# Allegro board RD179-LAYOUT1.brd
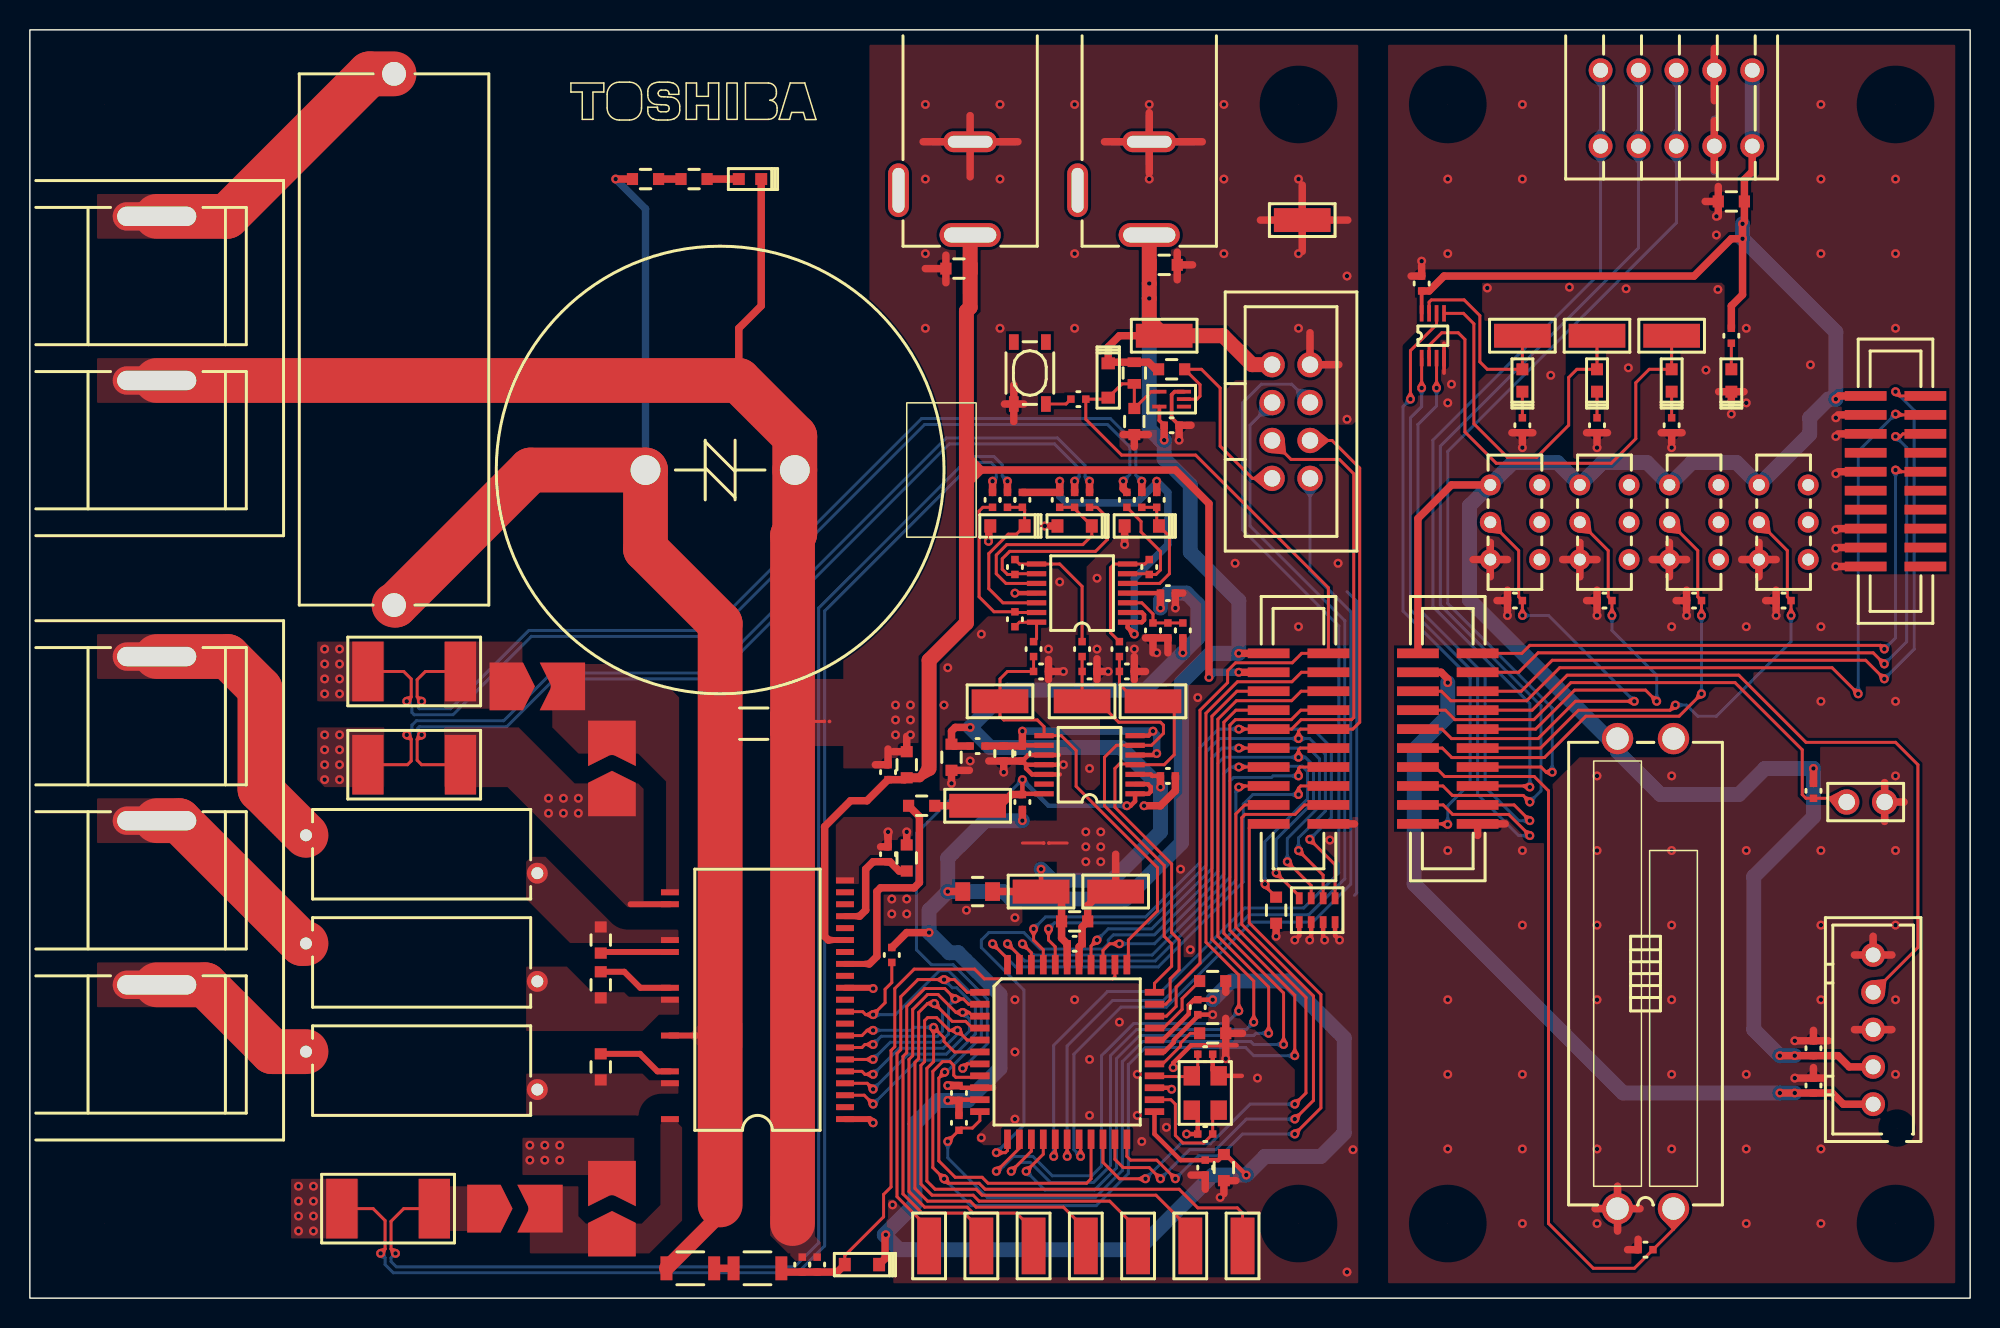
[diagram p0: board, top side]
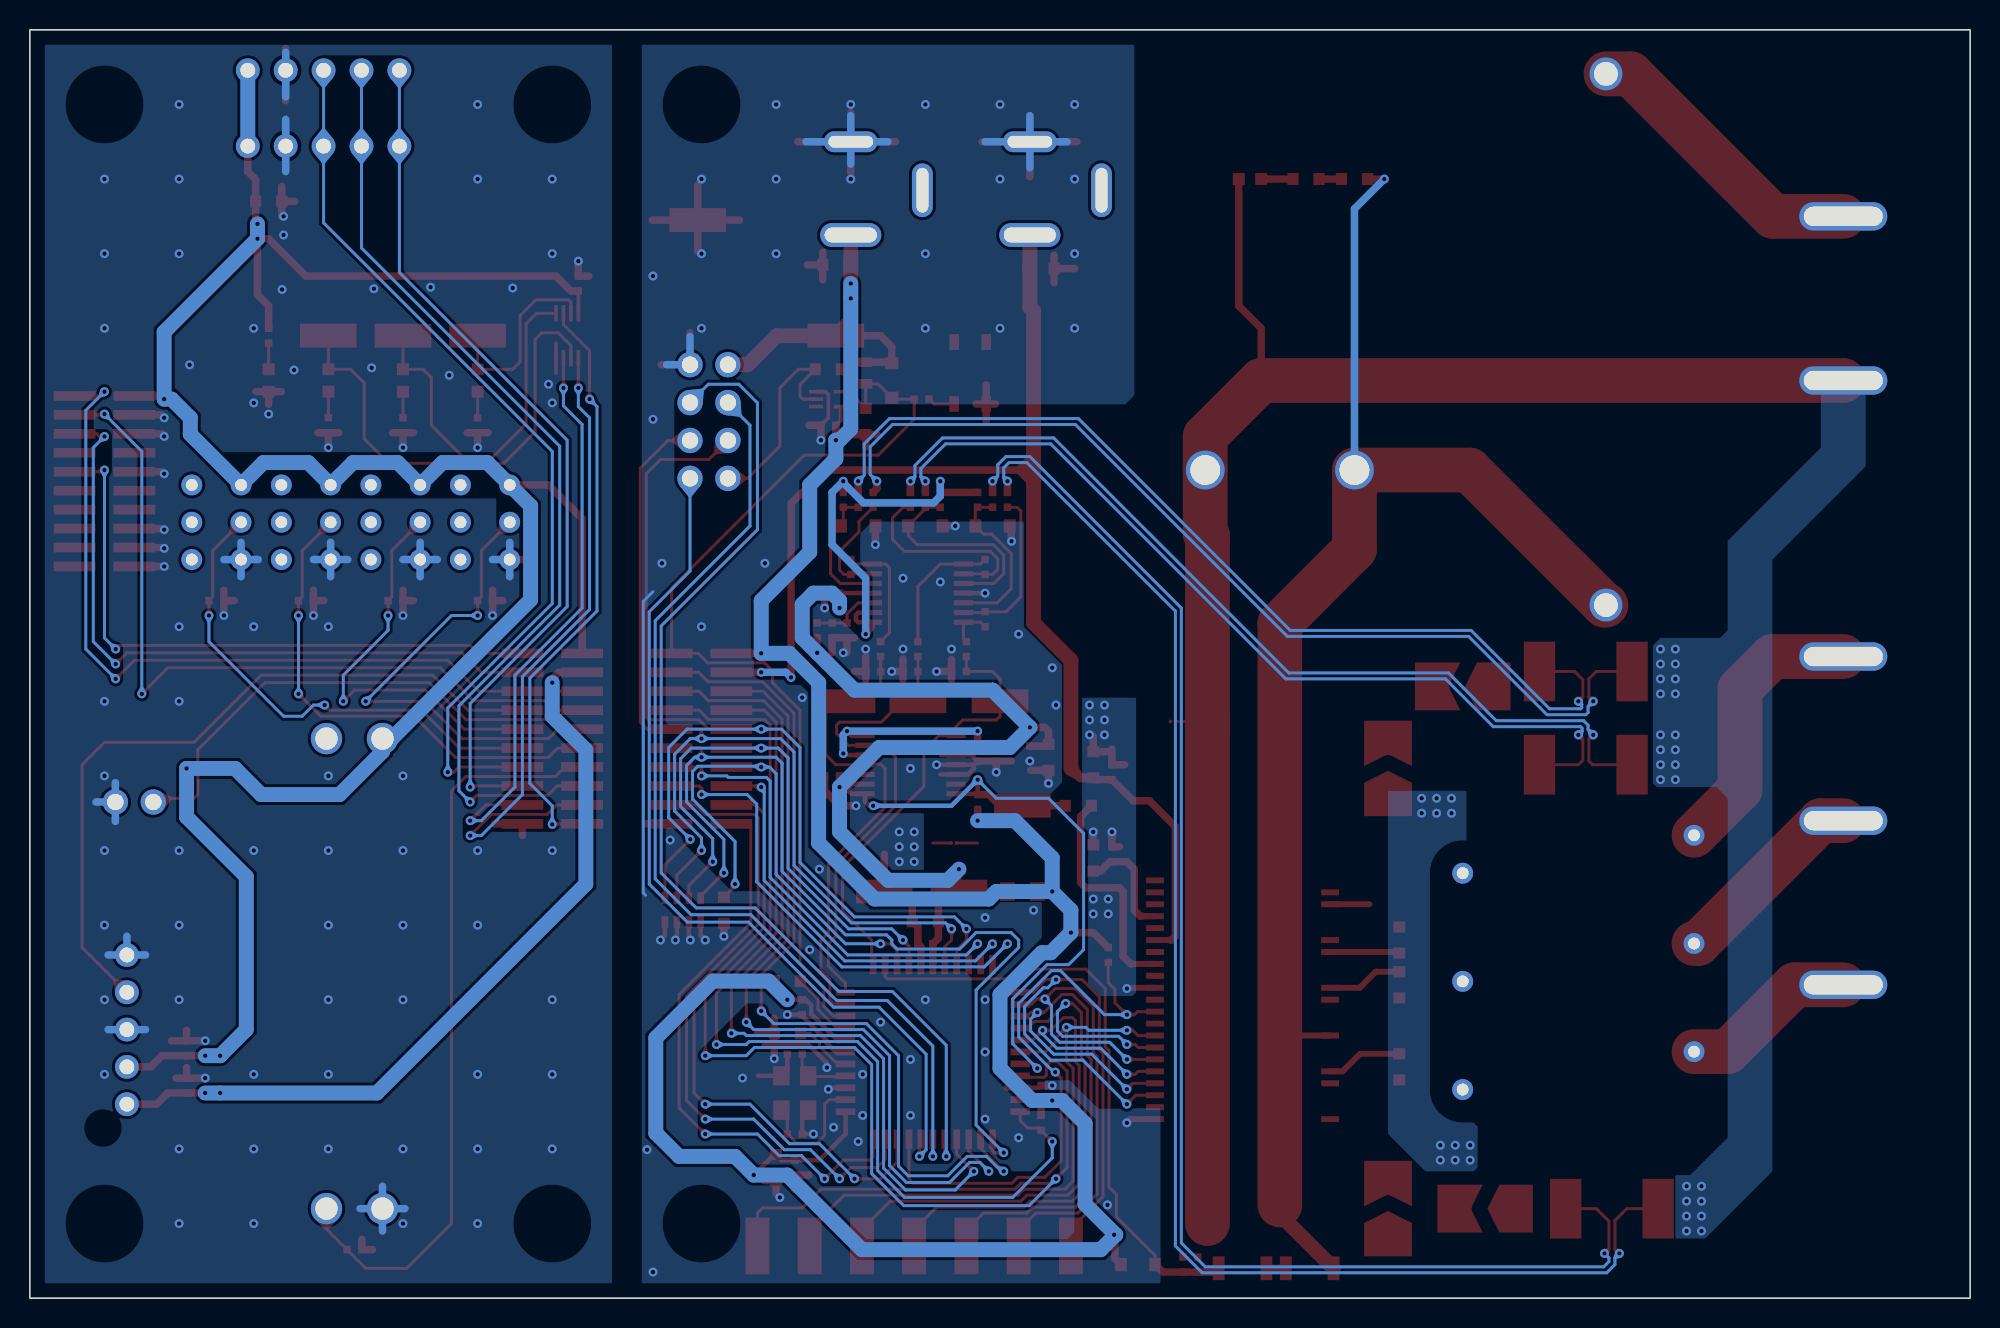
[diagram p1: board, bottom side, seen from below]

Outline 130 x 85 mm; copper layers: TOP, BOTTOM. Coordinates in mm from the lower left corner of the outline.
Outline path: rectangle 0,0 130,85

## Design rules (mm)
constraint set DEFAULT: 

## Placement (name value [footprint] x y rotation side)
C1  -  [CRC1608DEF_R]  58.75 35.75 90 top
C2  -  [CRC1005DEF_R]  57.5 35.25 90 top
C3  -  [CRC1005DEF_R]  62.25 13.75 90 top
C4  -  [CRC1005DEF_R]  78.75 8.75 270 top
C5  -  [CRC1608DEF_R]  80 8.75 270 top
C6  -  [CRC1005DEF_R]  70 23.75 0 top
C7  -  [CRC1608DEF_R]  70 25.25 0 top
C8  -  [CC3216DEF_R]  48.5 38.5 0 top
C9  -  [CRC1608DEF_R]  38.25 15.5 270 top
C10  -  [CRC1608DEF_R]  38.25 21 270 top
C11  -  [CRC1005DEF_R]  76.25 47.25 180 top
C12  -  [CRC1608DEF_R]  38.25 24 90 top
C13  -  [CRC1005DEF_R]  75.25 44.75 90 top
C14  -  [CRC1608DEF_R]  58.75 29.5 90 top
C15  -  [CRC1005DEF_R]  57.5 29.75 90 top
C16  -  [CRC1005DEF_R]  78.75 11 180 top
C18  -  [CRC1608DEF_R]  76 69.25 0 top
C19  -  [CRC1608DEF_R]  62.25 69 180 top
C20  -  [CRC1608DEF_R]  79.25 17.75 0 top
C21  -  [CRC1608DEF_R]  79.25 21.25 0 top
C22  -  [CRC1005DEF_R]  78.25 19.5 270 top
C24  -  [CRC1005DEF_R]  78.75 16.35 0 top
C25  -  [CRC1608DEF_R]  114 73.5 180 top
C26  -  [CRC1005DEF_R]  76.5 58.5 0 top
C27  -  [CRC1608DEF_R]  74 58.75 270 top
C29  -  [CRC1005DEF_R]  93.25 68 90 top
C30  -  [CRC1005DEF_R]  73.5 42 0 top
C31  -  [CRC1005DEF_R]  76.25 35 0 top
C32  -  [CRC1608DEF_R]  61.75 36.25 270 top
C33  -  [CRC1005DEF_R]  71 42 0 top
C34  -  [CRC1005DEF_R]  67.75 42 0 top
C35  -  [CRC1005DEF_R]  66.5 36.5 270 top
C36  -  [DDC300000]  46.25 55.5 0 top
C37  -  [CRC1005DEF_R]  52.75 2.25 90 top
C38  -  [CRC1005DEF_R]  108.25 3.25 180 top
C39  -  [CRC1005DEF_R]  119.5 16.75 90 top
C40  -  [CRC1005DEF_R]  119.5 14.25 90 top
D1  -  [CDUSC05_R]  55.75 2.25 180 top
D2  -  [CDUSC05_R]  72.25 61.5 270 top
D4  -  [CDUSC05_R]  74.5 51.75 180 top
D5  -  [CDUSC05_R]  70 51.75 180 top
D6  -  [CDUSC05_R]  65.5 51.75 180 top
F1  -  [DFU351200]  24.4 64.25 270 top
J1  -  [OTB_650_2P_R00]  8.5 63 270 top
J2  -  [OTB_650_3P_R00]  8.5 28 270 top
J3  -  [2DC_0005D100_R00]  63 71.25 90 top
J4  -  [ML_700_NV_5P_R00]  110 80 180 top
J5  -  [3220_20_0300_00_R00__1]  125 54.75 270 top
J6  -  [3220_20_0300_00_R00__1]  85 37.5 270 top
J7  -  [75869_332LF_R00]  84.5 58.75 270 top
J8  -  [B05B_XASK_1_A_R00]  123.5 18 270 top
J9  -  [3220_20_0300_00_R00__1]  95 37.5 270 top
J10  -  [2DC_0005D100_R00]  75 71.25 90 top
JP1  -  [PH_1X02SG_R00]  123 33.25 0 top
L1  -  [CL2125DEF_R]  63.5 27.25 180 top
L2  -  [DL146001]  26.25 15.25 0 top
L3  -  [DL146001]  26.25 22.5 0 top
L4  -  [DL146001]  26.25 29.75 0 top
LED1  -  [LTST_C190_R00_R]  100 61.5 90 top
LED2  -  [LTST_C190_R00_R]  105 61.5 90 top
LED3  -  [LTST_C190_R00_R]  110 61.5 90 top
LEDP1  -  [LTST_C190_R00_R]  48.25 75 180 top
LEDP2  -  [LTST_C190_R00_R]  114 61.5 90 top
NOREF  -  []  0 0 0 top
NOREF#2  -  []  143 -40 0 top
NOREF#3  -  [unnamed#2]  85 5 0 top
NOREF#4  -  [unnamed#2]  95 80 0 top
NOREF#5  -  [unnamed#2]  125 80 0 top
NOREF#6  -  []  0 -18.5 0 top
NOREF#7  -  [unnamed#2]  85 80 0 top
NOREF#8  -  [unnamed#2]  5 5 0 top
NOREF#9  -  []  36.25 79 0 top
NOREF#10  -  [unnamed#2]  95 5 0 top
NOREF#11  -  [unnamed#2]  5 80 0 top
NOREF#12  -  [unnamed#2]  125 5 0 top
R1  -  [CRC1608DEF_R]  41.25 75 0 top
R2  -  [CR3216DEF_R]  44.25 2 0 top
R3  -  [CRC1608DEF_R]  44.5 75 0 top
R4  -  [CR3216DEF_R]  48.75 2 0 top
R5  -  [CRC1005DEF_R]  51.75 2.25 90 top
R6  -  [CRC1005DEF_R]  77.25 44.75 90 top
R7  -  [CRC1005DEF_R]  76.25 44.75 270 top
R8  -  [CX000275_R]  68.1 30.5 180 top
R9  -  [CX000275_R]  53.4 38.65 180 top
R10  -  [CR643218_R]  24 6 0 top
R11  -  [CR643218_R]  25.75 35.75 0 top
R12  -  [CR643218_R]  25.75 42 0 top
R13  -  [CRC1005DEF_R]  57.75 23 90 top
R14  -  [CRC160858_R]  74 62 90 top
R15  -  [CRC1005DEF_R]  114 64.5 90 top
R16  -  [CRC1005DEF_R]  70.25 60.25 180 top
R17  -  [CRC1005DEF_R]  62.25 11.75 270 top
R18  -  [CRA321633_R]  86.25 26 0 top
R19  -  [CRC1608DEF_R]  83.5 26 270 top
R22  -  [CRC1005DEF_R]  119.5 34 270 top
R25  -  [CRC1005DEF_R]  100 58.5 270 top
R27  -  [CRC1005DEF_R]  75 49 270 top
R28  -  [CRC1005DEF_R]  73.5 53.5 90 top
R29  -  [CRC1005DEF_R]  73 43.5 90 top
R30  -  [CRC1005DEF_R]  105 58.5 270 top
R32  -  [CRC1005DEF_R]  74.5 53.5 90 top
R33  -  [CRC1005DEF_R]  63.5 37 0 top
R34  -  [CRC1005DEF_R]  75.5 53.5 90 top
R35  -  [CRC1005DEF_R]  66.5 33.25 90 top
R36  -  [CRC1005DEF_R]  110 58.5 270 top
R37  -  [CRC1005DEF_R]  66 49 270 top
R38  -  [CRC1005DEF_R]  71 53.5 90 top
R39  -  [CRC1005DEF_R]  70.5 43.5 90 top
R41  -  [CRC1005DEF_R]  70 53.5 90 top
R42  -  [CRC1005DEF_R]  69 53.5 90 top
R43  -  [CRC1608DEF_R]  59.75 33 0 top
R44  -  [CRC1005DEF_R]  66 45.5 90 top
R45  -  [CRC1005DEF_R]  64.5 53.5 90 top
R46  -  [CRC1005DEF_R]  67.25 43.5 90 top
R47  -  [CRC1005DEF_R]  65.5 53.5 90 top
R48  -  [CRC100512_R]  65.25 36.5 270 top
R49  -  [CRC1005DEF_R]  66.5 53.5 90 top
R50  -  [CRC1005DEF_R]  99.5 46.75 180 top
R51  -  [CRC1005DEF_R]  105.5 46.75 180 top
R52  -  [CRC1005DEF_R]  111.5 46.75 180 top
R53  -  [CRC1005DEF_R]  117.5 46.75 180 top
R54  -  [CRC1608DEF_R]  76.5 62.25 0 top
S_SW1  -  [IS_1250_R00]  99.5 52 270 top
S_SW2  -  [IS_1250_R00]  105.5 52 270 top
S_SW3  -  [IS_1250_R00]  111.5 52 270 top
S_SW4  -  [IS_1250_R00]  117.5 52 270 top
SJP1  -  [CJP0002116_R]  39 6 90 top
SJP2  -  [CJP0002116_R]  39 35.5 90 top
SJP3  -  [CJP0002116_R]  32.5 6 0 top
SJP4  -  [CJP0002116_R]  34 41 0 top
SW1  -  [SKRPABE010_R01_R]  67 62 90 top
TP1  -  [CTP321600_R]  81.25 3.5 270 top
TP3  -  [CTP321600_R]  74.25 3.5 270 top
TP4  -  [CTP321600_R]  67.25 3.5 270 top
TP5  -  [CTP321600_R]  60.25 3.5 90 top
TP6  -  [CTP321600_R]  85.25 72.25 180 top
TP7  -  [CTP321600_R]  76 64.5 0 top
TP8  -  [CTP321600_R]  72.75 27.25 180 top
TP9  -  [CTP321600_R]  67.75 27.25 180 top
TP10  -  [CTP321600_R]  75.25 40 180 top
TP11  -  [CTP321600_R]  63.5 33 180 top
TP12  -  [CTP321600_R]  70.5 40 0 top
TP13  -  [CTP321600_R]  65 40 0 top
TP14  -  [CTP321600_R]  63.75 3.5 90 top
TP15  -  [CTP321600_R]  70.75 3.5 90 top
TP16  -  [CTP321600_R]  77.75 3.5 90 top
TST1  -  [CTP321600_R]  100 64.5 0 top
TST2  -  [CTP321600_R]  105 64.5 0 top
TST3  -  [CTP321600_R]  110 64.5 0 top
U1  -  [SP031_0_8_00_R]  48.75 20 90 top
U2  -  [QP044_0_8_02_R]  69.5 16.5 270 top
U5  -  [CIC005_0_5_00_R]  76.5 60.25 90 top
U6  -  [SP014_0_65_06_R]  70.5 47.25 90 top
U7  -  [SP008_0_5_00_R]  94 64.5 0 top
U8  -  [SP014_0_65_06_R]  71 35.75 90 top
VR1  -  [RS15M111J002_R00]  108.25 21.75 90 top
Y1  -  [CXL322568_R]  78.75 13.75 90 top

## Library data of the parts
C1 C5 C7 C9 C10 C12 C14 C18-C21 C25 C27 C32 R1 R3 R19 R43 R54 = CRC-1608-DEF
C2-C4 C6 C11 C13 C15 C16 C22 C24 C26 C29-C31 C33-C35 C37-C40 R5-R7 R13 R15-R17 R22 R25 R27-R30 R32-R39 R41 R42 R44-R47 R49-R53 = CRC-1005-DEF
C8 = CC-3216-DEF
C36 = DDC-3000-00
D1 D2 D4-D6 = CD-USC-05
F1 = DFU-3512-00
J1 = OTB-650-2P_R00
J2 = OTB-650-3P_R00
J3 J10 = 2DC-0005D100_R00
J4 = ML-700-NV-5P_R00
J5 J6 J9 = 3220-20-0300-00_R00
J7 = 75869-332LF_R00
J8 = B05B-XASK-1-A_R00
JP1 = PH-1X02SG_R00
L1 = CL-2125-DEF
L2-L4 = DL-1460-01
LED1-LED3 LEDP1 LEDP2 = LTST-C190_R00
R2 R4 = CR-3216-DEF
R8 R9 = CX-0002-75
R10-R12 = CR-6432-18
R14 = CRC-1608-58
R18 = CRA-3216-33
R48 = CRC-1005-12
S_SW1-S_SW4 = IS-1250_R00
SJP1-SJP4 = CJP-0002-116
SW1 = SKRPABE010_R01
TP1 TP3-TP16 TST1-TST3 = HK-2-G
U1 = TPD4164F
U2 = TMPM374FWUG
U5 = TC7SZ07FE
U6 = AD8648ARUZ: alternate symbols: (U6_SP014_0_65_06_R)
U7 = TC7WH34FK
U8 = TS334IPT
VR1 = RS15M111J002_R00
Y1 = CXL-3225-68

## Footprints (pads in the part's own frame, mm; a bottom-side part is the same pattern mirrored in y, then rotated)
2DC_0005D100_R00
  oval 1.6x4.1 hole 1x3.5: 1(0,0)
  oval 1.4x3.6 hole 0.8x3: 2(6.25,0)
  oval 3.6x1.4 hole 3x0.8: 3(3,4.8)
3220_20_0300_00_R00__1
  rect 0.65x2.8 smd: 1(-5.715,-2) 2(-5.715,2) 3(-4.445,-2) 4(-4.445,2) 5(-3.175,-2) 6(-3.175,2) 7(-1.905,-2) 8(-1.905,2) 9(-0.635,-2) 10(-0.635,2) 11(0.635,-2) 12(0.635,2) 13(1.905,-2) 14(1.905,2) 15(3.175,-2) 16(3.175,2) 17(4.445,-2) 18(4.445,2) 19(5.715,-2) 20(5.715,2)
75869_332LF_R00
  round 1.7 hole 1.1: 1(-3.81,-1.27) 2(-3.81,1.27) 3(-1.27,-1.27) 4(-1.27,1.27) 5(1.27,-1.27) 6(1.27,1.27) 7(3.81,-1.27) 8(3.81,1.27)
B05B_XASK_1_A_R00
  round 0.01 hole 1.2 unplated: (6.6,1.6)
  round 1.6 hole 1: 1(5,0) 2(2.5,0) 3(0,0) 4(-2.5,0) 5(-5,0)
CC3216DEF_R
  rect 1x1.6 smd: 1(-1.6,0) 2(1.6,0)
CDUSC05_R
  rect 0.8x0.9 smd: 1(1.15,0) 3(-1.15,0)
CIC005_0_5_00_R
  rect 0.25x0.95 smd: 1(-0.5,-0.825) 2(0,-0.825) 3(0.5,-0.825) 4(0.5,0.825) 5(-0.5,0.825)
CJP0002116_R
  custom 0.76x0.76 smd: 1(-1.679,0) 2(1.679,0)
CL2125DEF_R
  rect 1x1.25 smd: 1(-1,0) 2(1,0)
CR3216DEF_R
  rect 0.8x1.6 smd: 1(-1.6,0) 2(1.6,0)
CR643218_R
  rect 2.1x4 smd: 1(-3.1,0) 2(3.1,0)
CRA321633_R
  rect 0.45x0.8 smd: 1(-1.2,-0.8) 2(-0.4,-0.8) 3(0.4,-0.8) 4(1.2,-0.8) 5(1.2,0.8) 6(0.4,0.8) 7(-0.4,0.8) 8(-1.2,0.8)
CRC1005DEF_R
  rect 0.5x0.5 smd: 1(-0.5,0) 2(0.5,0)
CRC1608DEF_R
  rect 0.75x0.8 smd: 1(-0.875,0) 2(0.875,0)
CRC100512_R
  rect 0.5x0.6 smd: 1(-0.5,0) 2(0.5,0)
CRC160858_R
  rect 0.65x0.9 smd: 1(-0.725,0) 2(0.725,0)
CTP321600_R
  rect 3.8x1.6 smd: 1(0,0)
CX000275_R
  custom 0.063x0.063 smd: 1(-0.175,0) 2(0.175,0)
CXL322568_R
  rect 1.3x1.1 smd: 1(-1.15,-0.9) 2(1.15,-0.9) 3(1.15,0.9) 4(-1.15,0.9)
DDC300000
  round 2.6 hole 2: 1(-5,0) 2(5,0)
DFU351200
  round 2.2 hole 1.6: 1(-17.8,0) 2(17.8,0)
DL146001
  round 1.4 hole 0.8: 1(-7.75,1.27) 2(7.75,-1.27)
IS_1250_R00
  round 1.4 hole 0.8: 1(-2.5,-1.65) 2(0,-1.65) 3(2.5,-1.65) 4(2.5,1.65) 5(0,1.65) 6(-2.5,1.65)
LTST_C190_R00_R
  rect 0.8x0.8 smd: 1(0.75,0) 2(-0.75,0)
ML_700_NV_5P_R00
  round 1.6 hole 1: 1(-5.4,-2.29) 1-2(-5.4,2.79) 2(-2.86,-2.29) 2-2(-2.86,2.79) 3(-0.32,-2.29) 3-2(-0.32,2.79) 4(2.22,-2.29) 4-2(2.22,2.79) 5(4.76,-2.29) 5-2(4.76,2.79)
OTB_650_2P_R00
  oval 1.9x5.9 hole 1.3x5.3: 1(-9.5,0) 2(1.5,0)
OTB_650_3P_R00
  oval 1.9x5.9 hole 1.3x5.3: 1(-15,0) 2(-4,0) 3(7,0)
PH_1X02SG_R00
  round 1.7 hole 1.1: 1(-1.27,0) 2(1.27,0)
QP044_0_8_02_R
  rect 0.45x1.3 smd: 1(-4,-5.85) 2(-3.2,-5.85) 3(-2.4,-5.85) 4(-1.6,-5.85) 5(-0.8,-5.85) 6(0,-5.85) 7(0.8,-5.85) 8(1.6,-5.85) 9(2.4,-5.85) 10(3.2,-5.85) 11(4,-5.85) 23(4,5.85) 24(3.2,5.85) 25(2.4,5.85) 26(1.6,5.85) 27(0.8,5.85) 28(0,5.85) 29(-0.8,5.85) 30(-1.6,5.85) 31(-2.4,5.85) 32(-3.2,5.85) 33(-4,5.85)
  rect 1.3x0.45 smd: 12(5.85,-4) 13(5.85,-3.2) 14(5.85,-2.4) 15(5.85,-1.6) 16(5.85,-0.8) 17(5.85,0) 18(5.85,0.8) 19(5.85,1.6) 20(5.85,2.4) 21(5.85,3.2) 22(5.85,4) 34(-5.85,4) 35(-5.85,3.2) 36(-5.85,2.4) 37(-5.85,1.6) 38(-5.85,0.8) 39(-5.85,0) 40(-5.85,-0.8) 41(-5.85,-1.6) 42(-5.85,-2.4) 43(-5.85,-3.2) 44(-5.85,-4)
RS15M111J002_R00
  round 2.1 hole 1.5: 1(-15.75,1.875) 2(-15.75,-1.875) 3(15.75,1.875) 4(15.75,-1.875)
SKRPABE010_R01_R
  rect 1.05x0.65 smd: 1(2.075,-1.075) 2(-2.075,-1.075) 3(2.075,1.075) 4(-2.075,1.075)
SP008_0_5_00_R
  rect 0.25x1.1 smd: 1(-0.75,-1.5) 2(-0.25,-1.5) 3(0.25,-1.5) 4(0.75,-1.5) 5(0.75,1.5) 6(0.25,1.5) 7(-0.25,1.5) 8(-0.75,1.5)
SP014_0_65_06_R
  rect 0.35x1.3 smd: 1(-1.95,-3.05) 2(-1.3,-3.05) 3(-0.65,-3.05) 4(0,-3.05) 5(0.65,-3.05) 6(1.3,-3.05) 7(1.95,-3.05) 8(1.95,3.05) 9(1.3,3.05) 10(0.65,3.05) 11(0,3.05) 12(-0.65,3.05) 13(-1.3,3.05) 14(-1.95,3.05)
SP031_0_8_00_R
  rect 0.4x1.2 smd: 1(-8,5.865) 2(-5.6,5.865) 3(-4.8,5.865) 4(-2.4,5.865) 5(0,5.865) 6(0.8,5.865) 7(3.2,5.865) 8(4,5.865) 9(6.4,5.865) 10(7.2,5.865) 11(8,-5.865) 12(7.2,-5.865) 13(6.4,-5.865) 14(5.6,-5.865) 15(4.8,-5.865) 16(4,-5.865) 17(3.2,-5.865) 18(2.4,-5.865) 19(1.6,-5.865) 20(0.8,-5.865) 21(0,-5.865) 22(-0.8,-5.865) 23(-1.6,-5.865) 24(-2.4,-5.865) 25(-3.2,-5.865) 26(-4,-5.865) 27(-4.8,-5.865) 28(-5.6,-5.865) 29(-6.4,-5.865) 30(-7.2,-5.865) 31(-8,-5.865)
unnamed#2
  round 0.01 hole 3.2 unplated: (0,0)

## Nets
AGND: C6.2 C7.2 C11.1 C13.1 C30.2 C31.2 C32.2 C33.2 C34.2 C35.2 D4.1 D5.1 D6.1 R7.2 R8.1 R48.2 TP8.1 U2.38 U6.11 U8.10 U8.11 U8.12
AVDD: C6.1 C7.1 C11.2 C31.1 C32.1 L1.1 R6.1 R33.1 TP9.1 U2.39 U6.4 U8.3
GND: C1.2 C2.2 C3.2 C4.2 C5.2 C14.2 C15.2 C16.2 C18.2 C19.2 C20.2 C21.2 C22.2 C24.2 C26.2 C27.2 J3.2 J6.20 J7.2 J10.2 R8.2 R9.1 R18.1 R18.2 R18.3 R18.4 R19.2 SW1.4 TP6.1 U1.11 U1.20 U1.31 U2.9 U2.25 U2.28 U5.3 Y1.2 Y1.4
GNDX: C25.2 C29.2 C38.2 C39.2 C40.2 J4.2 J4.2-2 J5.3 J5.5 J5.9 J5.15 J5.17 J5.19 J8.3 J8.5 J9.20 JP1.2 LEDP2.2 R25.2 R30.2 R36.2 R50.2 R51.2 R52.2 R53.2 S_SW1.3 S_SW2.3 S_SW3.3 S_SW4.3 U7.4 VR1.1
PGND: C8.2 C36.2 C37.2 J1.2 LEDP1.2 R5.2 R9.2 R10.1 R11.1 R12.1 R28.2 R38.2 R45.2
VDD: C3.1 C4.1 C5.1 C18.1 C22.1 C26.1 D1.3 D2.3 J6.1 J7.1 J10.1 L1.2 R13.2 R14.2 R17.1 R35.1 R54.1 TP7.1 U2.10 U2.23 U2.29 U5.5
VDDX: C25.1 C29.1 C39.1 J4.1 J4.1-2 J5.1 J8.2 J9.1 R15.2 R22.1 S_SW1.1 S_SW2.1 S_SW3.1 S_SW4.1 U7.8 VR1.3
+15: C1.1 C2.1 C19.1 J3.1 J6.3 U1.16
+15X: C40.1 J8.1 J9.3
AD_UP_1: C30.1 R29.1 TP10.1 U2.32 U8.4
AD_VDC_1: C37.1 D1.1 R4.2 R5.1 U2.35
AD_VP_1: C33.1 R39.1 TP12.1 U2.33 U8.6
AD_WP_1: C34.1 R46.1 TP13.1 U2.34 U8.8
COMMD: J6.10 J7.6 R18.6 U2.40
DIAG: R43.1 U1.18
GPIO_MAIN: J7.8 U2.18
KEY_1: J6.9 J7.5 R18.5 U2.41
KEY_3: J6.11 R18.7 U2.37
KEY_4: J6.12 R18.8 U2.12
KEY_A: J6.13 R19.1 U2.36
KEYX_1: J9.9 R50.1 S_SW1.2
KEYX_2: J9.10 R51.1 S_SW2.2
KEYX_3: J9.11 R52.1 S_SW3.2
KEYX_4: J9.12 R53.1 S_SW4.2
KEYX_A: C38.1 J9.13 VR1.2
LED1: J6.17 U2.20
LED1X: J9.17 U7.1
LED2: J6.18 U2.21
LED2X: J9.18 U7.3
LED3: J6.19 U2.22
LED3X: J9.19 U7.6
NBOOT: J6.7 R17.2 U2.11
NBOOTX: J9.7 JP1.1 R22.2
NEMG: R35.2 R43.2 TP11.1 U2.7 U8.1 U8.2 U8.14
NRESET: C27.1 D2.1 J6.2 R14.1 R16.1 U2.31 U5.4
NRESETX: J5.10 J9.2
NRESIN: J7.7 R54.2 U5.2
NSD: R13.1 U1.22 U2.19
NSYNC_SPI: J6.14 U2.42
NSYNC_SPIX: J4.3 J4.3-2 J9.14
RELAY: J6.8 TP1.1 U2.8
RELAYX: J8.4 J9.8
RXD_UA_MCU: J7.3 U2.17
SCLK_SPI: J6.16 U2.44
SCLK_SPIX: J4.5 J4.5-2 J9.16
SDO_SPI: J6.15 U2.43
SDO_SPIX: J4.4 J4.4-2 J9.15
SWCLK: J6.5 U2.14
SWCLKX: J5.4 J9.5
SWDIO: J6.6 U2.15
SWDIOX: J5.2 J9.6
SWV: J6.4 U2.13
SWVX: J5.6 J9.4
TXD_UA_MCU: J7.4 U2.16
UH_1: TP5.1 U1.29 U2.1
UL_1: TP14.1 U1.26 U2.2
VH_1: TP4.1 U1.28 U2.3
VL_1: TP15.1 U1.25 U2.4
VP+: C8.1 C36.1 F1.2 R1.1 R2.1 U1.4
WH_1: TP3.1 U1.27 U2.5
WL_1: TP16.1 U1.24 U2.6
N524300: C24.1 U2.26 Y1.3
N524312: C16.1 U2.24 Y1.1
N530340: C20.1 U2.27
N530678: C21.1 U2.30
N538715: C9.1 U1.3
N538730: C9.2 L2.2 U1.2
N538933: C10.2 L3.2 U1.5
N539007: C10.1 U1.6
N539077: C12.2 L4.2 U1.8
N539151: C12.1 U1.7
N541275: J2.2 L3.1
N541304: J2.3 L2.1
N541340: J2.1 L4.1
N542318: F1.1 J1.1
N545140: SJP2.2 SJP4.2 U1.10
N545527: R11.2 R41.2 SJP1.2 SJP2.1 U1.9
N545615: SJP1.1 SJP3.2 U1.1
N16763341: C14.1 C15.1 U1.14
N16816065: C35.1 R33.2 R48.1 U8.5 U8.7 U8.9
N16817615: D5.3 R41.1 R42.1 U6.10
N16817617: R37.1 R39.2 U6.8
N16817619: R37.2 R38.1 U6.9
N16818945: D4.3 R32.1 R34.1 U6.5
N16818947: R27.1 R29.2 U6.7
N16818953: R27.2 R28.1 U6.6
N16823954: R34.2 R42.2 R49.2 U6.1 U6.2
N16824265: D6.3 R47.1 R49.1 U6.12
N16827190: R12.2 R32.2 SJP4.1
N16827301: R10.2 R47.2 SJP3.1
N16845509: LED1.1 TST1.1 U7.7
N16847149: LED3.1 TST3.1 U7.2
N16847386: LED2.1 TST2.1 U7.5
N16936899: LEDP1.1 R3.2
N16997175: C13.2 R6.2 R7.1 U6.3
N17594442: R44.2 R45.1 U6.13
N17594625: R44.1 R46.2 U6.14
N89949821: R16.2 SW1.2
N168435951: R1.2 R3.1
N168438761: R2.2 R4.1
N168456521: LED1.2 R25.1
N168457540: LED3.2 R36.1
N168470940: LEDP2.1 R15.1
N168482340: LED2.2 R30.1

Pads without a net: J3 3; J5 7 8 11 12 13 14 16 18 20; J10 3; S_SW1 4 5 6; S_SW2 4 5 6; S_SW3 4 5 6; S_SW4 4 5 6; SW1 1 3; U1 12 13 15 17 19 21 23 30; U5 1; U8 13; VR1 4

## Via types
v1: diameter 0.6, hole 0.3, TOP to BOTTOM, 345 vias

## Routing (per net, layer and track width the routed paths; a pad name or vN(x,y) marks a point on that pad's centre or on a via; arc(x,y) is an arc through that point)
AGND: length 43.1
  TOP w0.2: 68.28,30.5 69.5,30.5
  TOP w0.3: 69,35.1 U8.12 67.15,35.1 66.75,35.5 66.75,35.75 ; 66.75,35.75 C35.2 66.9,36.4 U8.10 68.95,36.4 ; 66.75,35.75 U8.11 69,35.75 ; U6.11 v1(66,47.25)
  TOP w0.5: U2.38 70.3,23.55 C6.2 70.5,24.88 C7.2 70.88,26.3 71.83,27.25 TP8.1 72.75,29.75 ; C33.2 v1(72.25,42) ; C33.2 71.5,42.85 ; C33.2 71.5,41.45 ; C13.1 R7.2 76.25,43.25 ; C13.1 75.25,43.25 ; C13.1 74.75,44.25 ; C34.2 v1(69.25,42) ; C34.2 68.25,42.8 ; C34.2 68.25,41.45 ; v1(74.65,33) 75.75,33 76.75,34 C31.2 ; C30.2 74,41.45 ; C30.2 74.75,42 ; C30.2 74,43 ; C35.2 R48.2 ; R48.2 v1(65.25,35.25) ; R48.2 64.25,36 ; D4.1 v1(73.35,50.5) ; D5.1 v1(68,51.75) ; 77.25,47.25 C11.1 v1(76.75,46.25) ; v1(64.22,50.73) 64.25,50.7 64.25,51.65 D6.1 ; v1(61.75,34.5) C32.2 62.95,35.38
  vias: v1(61.25,39.75) v1(61.5,42.25) v1(63,36) v1(63.75,44.5) v1(68.25,43.5) v1(69,48) v1(69.25,35.75) v1(70.75,31.25) v1(70.75,30.25) v1(70.75,29.25) v1(71,35.5) v1(71.5,48.25) v1(71.5,43.5) v1(71.75,31.25) v1(71.75,30.25) v1(71.75,29.25) v1(74,43.5) v1(75.5,43.25)
AVDD: length 71.9
  TOP w0.3: U6.4 C11.2 ; TP9.1 v1(67.75,28.75) ; U8.3 75.1,35.1 75.2,35 C31.1
  TOP w0.5: U2.39 C6.1 69.12,24.12 C7.1 69.12,27.11 68.98,27.25 TP9.1 L1.1 ; R33.1 61.88,37 C32.1 61.75,38 62,38.25 v1(63,38.25) ; C11.2 v1(75.75,46.25) ; C31.1 v1(75.75,34.25) ; R6.1 v1(77.25,43.25)
  BOTTOM w1: v1(75.75,46.25) 75.75,46.75 76.25,47.25 77.5,47.25 78.25,46.5 78.25,44.25 v1(77.25,43.25) 74.75,40.75 65.5,40.75 v1(63,38.25) 64.35,36.9 73.1,36.9 v1(75.75,34.25) 75.75,31.25 72.5,28 68.5,28 v1(67.75,28.75)
GND: length 142.2
  TOP w0.2: R8.2 66.5,30.5
  TOP w0.25: C26.2 76.5,59 76.5,60.55 76.7,60.75 U5.3
  TOP w0.3: v1(77.5,11) C16.2 78.25,12.2 Y1.4 ; v1(85.75,24) 85.85,24.1 R18.2 ; C3.2 62.4,14.1 63.15,14.1 ; R18.3 86.65,24.1 v1(86.75,24) ; C24.2 79.25,15.3 Y1.2 81.2,14.9 ; U2.28 76,16.5 76.65,17.15 76.65,17.3 78.25,18.9 C22.2 v1(79.25,19) ; U2.25 76.4,14.1 v1(76.5,14) ; R18.1 85.05,24.3 v1(84.75,24) ; R18.4 87.45,24.3 v1(87.75,24) ; v1(76.6,15.45) 76.6,15.75 77.8,16.95 80.85,16.95
  TOP w0.4: 64.55,14.1 U2.9 63.15,14.1 ; U1.20 56.45,20.8 v1(56.5,20.75) ; U1.31 56.25,12 v1(56.5,11.75)
  TOP w0.5: 85.77,64.7 J7.2 87.7,62.56 ; C18.2 76.88,68.25 ; C18.2 77.9,69.25 ; C18.2 76.88,70.1 ; v1(77,57.5) C26.2 77.8,58.5 ; v1(57.5,31.25) C15.2 57,30.25 ; 78.75,7.3 C4.2 77.8,8.25 ; SW1.4 65.92,61.2 ; SW1.4 65.92,58.75 ; SW1.4 65.3,59.92 ; SW1.4 66.6,59.92 ; C19.2 60,69 ; C19.2 61.38,68.05 ; C19.2 61.38,69.9 ; R19.2 v1(83.5,24.25) ; J3.2 63,79.25 ; J3.2 63,75.15 ; J3.2 66.2,77.5 ; J3.2 59.85,77.5 ; TP6.1 88.3,72.25 ; TP6.1 85.25,70.15 ; TP6.1 82.45,72.25 ; TP6.1 85.25,74.6 ; v1(61.5,14.25) C3.2 ; J10.2 78.55,77.5 ; J10.2 75,79.45 ; J10.2 72,77.5 ; J10.2 75,75.4 ; 57.5,36.8 C2.2 56.65,35.75 ; 58.75,37.65 C1.2 57.85,36.62 ; C27.2 73.25,57.88 ; C27.2 74.95,57.88 ; C27.2 74,57.05 ; C21.2 80.12,20.5 ; 81.25,17.75 C20.2 ; C20.2 v1(80.12,16.05) ; C20.2 80.12,18.75 ; J6.20 88.75,31.79 ; 80,7 C5.2 80.8,7.88 ; v1(58.75,31.25) C14.2
  BOTTOM w0.2: 88.25,47.35 88.9,46.7 88.9,27.15 88.75,27
  BOTTOM w0.5: J10.2 78,77.5 ; J10.2 72.5,77.5 ; J10.2 75,76 ; J10.2 75,79.25 ; J3.2 60.5,77.5 ; J3.2 63,79.25 ; J3.2 63,75.75 ; J3.2 66,77.5 ; 85.77,64.45 J7.2 87.35,62.56
  vias: v1(57.75,26.75) v1(57.75,25.75) v1(57.8,6.25) v1(58,39.75) v1(58,38.75) v1(58,37.75) v1(58.75,26.75) v1(58.75,25.75) v1(59,39.75) v1(59,38.75) v1(59,37.75) v1(60,80) v1(60,75) v1(60,70) v1(60,65) v1(62.75,26) v1(63.75,10.75) v1(65,80) v1(65,75) v1(65,65) v1(66,25.5) v1(66,20) v1(66,16.5) v1(66,12) v1(70,80) v1(70,70) v1(70,65) v1(70,20) v1(71,16) v1(71,12.25) v1(73,18.5) v1(74.2,15) v1(74.2,12.25) v1(74.5,10.5) v1(75,80) v1(75,75) v1(76.15,11.45) v1(77.1,28.75) v1(77.75,23.35) v1(78.25,40.25) v1(79.75,6.75) v1(80,80) v1(80,75) v1(80,70) v1(80.75,49.25) v1(82.25,14.75) v1(85,75) v1(85,70) v1(85,65) v1(85,45) v1(87.1,30.7) v1(87.65,49.25) v1(88.25,68.5) v1(88.25,58.9) v1(88.25,1.75) v1(88.65,9.95)
GNDX: length 125.5
  TOP w0.25: 94.75,62 U7.4 94.75,64
  TOP w0.5: C25.2 113.12,72.5 ; C25.2 112.25,73.5 ; C25.2 113.12,74.5 ; R30.2 105,57.3 ; R30.2 105.7,58 ; R30.2 104.3,58 ; JP1.2 125.57,33.25 ; JP1.2 124.27,34.55 ; JP1.2 124.27,31.95 ; 107.75,3.95 C38.2 107.05,3.25 ; S_SW2.3 103.85,48.35 ; S_SW2.3 105,49.5 ; S_SW2.3 103.85,50.65 ; S_SW2.3 102.7,49.5 ; VR1.1 107.88,6 ; VR1.1 104.88,6 ; VR1.1 106.38,4.5 ; VR1.1 106.38,7.5 ; S_SW1.3 99,49.5 ; S_SW1.3 97.85,48.35 ; S_SW1.3 97.85,50.65 ; S_SW1.3 96.7,49.5 ; S_SW4.3 117,49.5 ; S_SW4.3 115.85,48.35 ; S_SW4.3 114.7,49.5 ; S_SW4.3 115.85,50.65 ; LEDP2.2 114,59.9 ; LEDP2.2 113.15,60.75 ; LEDP2.2 114.85,60.75 ; J5.17 121.15,50.3 ; S_SW3.3 109.85,48.35 ; S_SW3.3 111,49.5 ; S_SW3.3 108.7,49.5 ; S_SW3.3 109.85,50.65 ; R51.2 105,46.05 ; R51.2 104.3,46.75 ; R51.2 105,47.45 ; R50.2 98.3,46.75 ; R50.2 99,46.05 ; R50.2 99,47.45 ; J5.15 121.15,51.58 ; C39.2 119.5,17.95 ; C39.2 120.5,17.25 ; C39.2 v1(118.25,17.25) ; J5.19 121.15,49.03 ; 112.86,83.75 J4.2 112.86,80.25 ; R52.2 111,47.45 ; R52.2 110.3,46.75 ; R52.2 111,46.05 ; 112.86,75.6 J4.2-2 112.86,78.9 ; R53.2 117,46.05 ; R53.2 116.3,46.75 ; R53.2 117,47.45 ; R36.2 109.3,58 ; R36.2 110.7,58 ; R36.2 110,57.3 ; 93.25,69.2 C29.2 92.55,68.5 ; J5.9 121.15,55.38 ; 97,31.01 J9.20 98.85,31.79 ; J8.5 124.75,23 ; J8.5 123.5,24.25 ; J8.5 122.25,23 ; 122.25,18 J8.3 124.75,18 ; R25.2 100.7,58 ; R25.2 99.3,58 ; R25.2 100,57.3 ; J5.3 121.15,59.2 ; C40.2 119.5,15.45 ; C40.2 v1(118.25,14.75) ; C40.2 120.2,14.75 ; J5.5 121.15,57.92
  BOTTOM w0.5: J8.5 124.75,23 ; J8.5 122.25,23 ; J8.5 123.5,24.25 ; 124.75,18 J8.3 122.25,18 ; S_SW2.3 102.7,49.5 ; S_SW2.3 105,49.5 ; S_SW2.3 103.85,50.65 ; S_SW2.3 103.85,48.35 ; 112.86,83.5 J4.2 112.86,80.5 ; S_SW3.3 111,49.5 ; S_SW3.3 108.7,49.5 ; S_SW3.3 109.85,50.65 ; S_SW3.3 109.85,48.35 ; VR1.1 106.38,4.5 ; VR1.1 107.88,6 ; VR1.1 104.88,6 ; VR1.1 106.38,7.5 ; S_SW4.3 114.7,49.5 ; S_SW4.3 115.85,50.65 ; S_SW4.3 115.85,48.35 ; S_SW4.3 117,49.5 ; 112.86,79 J4.2-2 112.86,75.5 ; JP1.2 125.57,33.25 ; JP1.2 124.27,34.55 ; JP1.2 124.27,31.95 ; S_SW1.3 97.85,48.35 ; S_SW1.3 99,49.5 ; S_SW1.3 97.85,50.65
  vias: v1(93.25,69.5) v1(95,75) v1(95,70) v1(95,60) v1(95,30) v1(95,20) v1(95,15) v1(95,10) v1(95.25,61.25) v1(97.65,67.7) v1(99,45.75) v1(100,80) v1(100,75) v1(100,57) v1(100,30) v1(100,25) v1(100,15) v1(100,10) v1(100,5) v1(101.9,61.85) v1(103.15,67.75) v1(105,57) v1(105,45.75) v1(105,35) v1(105,30) v1(105,25) v1(105,20) v1(105,10) v1(105,5) v1(106.95,67.65) v1(107.1,62.35) v1(110,57) v1(110,45) v1(110,35) v1(110,30) v1(110,25) v1(110,20) v1(110,15) v1(110,10) v1(111,45.75) v1(112.3,62.2) v1(113,72.5) v1(113,71.25) v1(113.1,67.6) v1(114,59.25) v1(115,65) v1(115,60) v1(115,45) v1(115,30) v1(115,15) v1(115,10) v1(115,5) v1(117,45.75) v1(119.3,62.55) v1(120,80) v1(120,75) v1(120,70) v1(120,45) v1(120,40) v1(120,30) v1(120,25) v1(120,20) v1(120,10) v1(120,5) v1(121,59) v1(121,57.75) v1(121,55.25) v1(121,51.5) v1(121,50.25) v1(121,49.03) v1(125,75) v1(125,70) v1(125,65) v1(125,40) v1(125,35) v1(125,30) v1(125,25) v1(125,20) v1(125,15)
PGND: length 338.6
  TOP w0.2: R11.1 25.3,35.75 25.55,36 25.55,37.45 v1(25.25,37.75) ; R12.1 25.05,42 25.55,41.5 25.55,40.3 v1(25.25,40) ; C8.2 50.25,38.65 R9.2 ; v1(23.5,3) 23.8,3.3 23.8,5.2 23,6 R10.1
  TOP w0.5: R28.2 73.25,54.25 v1(73.25,54.75) ; v1(71,54.75) R38.2 ; 47.5,61.5 47.5,65 49,66.5 LEDP1.2 ; v1(64.5,54.75) R45.2
  TOP w3: J1.2 47.5,61.5 51.25,57.75 C36.2 51.25,51.25 51.1,51.1 51.1,5
  BOTTOM w0.2: v1(25.25,40) 25.6,39.65 25.6,39.25 25.75,39.1 28.35,39.1 33.6,44.35 45.75,44.35 59.95,58.55 72.2,58.55 73.7,57.05 73.7,55.2 v1(73.25,54.75) ; v1(25.25,37.75) 25.6,38.1 25.6,38.4 25.9,38.7 31.75,38.7 34.95,41.9 45.65,41.9 61.4,57.65 68.85,57.65 70.7,55.8 70.7,55.05 v1(71,54.75) ; v1(23.5,3) 23.8,2.7 23.8,2.25 24.35,1.7 51.45,1.7 53.25,3.5 53.25,46.05 63.2,56 64.4,56 64.75,55.65 64.75,55 v1(64.5,54.75)
  vias: v1(18,7.5) v1(18,6.5) v1(18,5.5) v1(18,4.5) v1(19,7.5) v1(19,6.5) v1(19,5.5) v1(19,4.5) v1(19.75,43.5) v1(19.75,42.5) v1(19.75,41.5) v1(19.75,40.5) v1(19.75,37.75) v1(19.75,36.75) v1(19.75,35.75) v1(19.75,34.75) v1(20.75,43.5) v1(20.75,42.5) v1(20.75,41.5) v1(20.75,40.5) v1(20.75,37.75) v1(20.75,36.75) v1(20.75,35.75) v1(20.75,34.75)
VDD: length 203.5
  TOP w0.25: U5.5 75.67,58.83 C26.1
  TOP w0.3: U2.10 62.3,13.3 C3.1 ; v1(81.5,8.25) 80.12,9.62 C5.1 79.62,9.25 C4.1 77.1,9.25 75.35,11 U2.23 ; U2.29 75.9,17.3 77.65,19.05 77.65,19.65 78,20 C22.1 v1(79.25,20)
  TOP w0.5: R13.2 58.75,24.5 v1(60.25,24.5) ; R35.1 v1(66.5,32) ; D1.3 57.3,2.65 57.3,4.25 v1(57.35,4.25) ; L1.2 v1(61.5,27.25) ; J6.1 v1(81,43.22) ; v1(61.5,13.25) C3.1 R17.1 ; R54.1 75.42,62.25 74.95,62.73 R14.2 72.33,62.73 D2.3 72.25,63.75 73,64.5 TP7.1 ; C26.1 v1(76,57.5)
  TOP w1: J10.1 v1(75,68) v1(75,67) 75,65.5 TP7.1 79.95,64.5 81.89,62.56 J7.1
  BOTTOM w1: v1(75,68) v1(75,67) 75,58.25 75.75,57.5 v1(76,57.5) 76,56.25 77.75,54.5 77.75,50 81,46.75 v1(81,43.22) 79.11,43.22 77.15,41.25 77.15,30.5 73.4,26.75 65.75,26.75 65.25,27.25 v1(61.5,27.25) ; 57.25,4.25 58.25,3.25 74.25,3.25 79.25,8.25 v1(81.5,8.25) 82.75,9.5 86.5,9.5 88.06,11.06 88.06,17.44 84.25,21.25 80.5,21.25 v1(79.25,20) ; 57.25,4.25 59.3,6.3 59.3,11.7 60.85,13.25 v1(61.5,13.25) 62.85,13.25 65,15.4 65,20.35 62.2,23.15 61.6,23.15 v1(60.25,24.5) 60.25,26 v1(61.5,27.25) ; 57.25,4.25 v1(57.35,4.25) ; v1(61.5,27.25) 61.5,29.5 64,32 v1(66.5,32)
VDDX: length 171.6
  TOP w0.25: U7.8 C29.1
  TOP w0.5: S_SW1.1 95.25,54.5 93,52.25 J9.1 ; J4.1-2 115.4,75.5 114.88,74.97 C25.1 114.88,72.12 v1(114.75,72) v1(114.75,71) ; R15.2 114,66.5 114.75,67.25 v1(114.75,71) ; v1(114.75,71) 114,71 111.5,68.5 94.75,68.5 93.75,67.5 C29.1 ; v1(121,60.25) 121.22,60.47 J5.1 ; J8.2 121.9,15.5 121.15,16.25 C39.1 v1(118.25,16.25) v1(117.25,16.25) ; v1(119.5,35.5) R22.1
  BOTTOM w1: v1(118.25,16.25) v1(117.25,16.25) 115.5,18 115.5,28.25 119.5,32.25 v1(119.5,35.5) 116.25,35.5 114.5,33.75 109.25,33.75 106.38,36.62 VR1.3 105.75,37.5 96.45,46.8 96.45,53.1 S_SW1.1 99.35,56 102.35,56 S_SW2.1 105.35,56 108.35,56 S_SW3.1 111.35,56 114.35,56 S_SW4.1 119.25,57.9 119.25,59 120.5,60.25 v1(121,60.25) 121,64.75 v1(114.75,71) v1(114.75,72) ; J4.1-2 J4.1
+15: length 90.1
  TOP w0.4: U1.16 53.5,24
  TOP w0.5: 62.75,55.5 63.75,55.5 ; 63.75,55.5 62.75,56.5 ; 63.75,55.5 76.75,55.5 79,53.25 v1(79,41.6) ; 63.75,55.5 62.75,54.5 ; 53.5,24 53.25,24.25 53.25,31.6 54.98,33.34 56.09,33.34 C2.1 58.62,34.75 C1.1 ; J6.3 v1(81,41.95)
  TOP w0.6: 60.25,35.5 59.62,34.88 C1.1
  TOP w1: 60.25,35.5 60.25,42.75 62.75,45.25 62.75,66.15 63,66.4 J3.1
  BOTTOM w0.5: v1(81,41.95) 79.34,41.95 v1(79,41.6)
+15X: length 54.7
  TOP w0.5: v1(95,41.25) 95,41.5 94.56,41.95 J9.3 ; v1(117.25,13.75) v1(118.25,13.75) C40.1 120.75,13.75 121.5,13 J8.1
  BOTTOM w1: v1(118.25,13.75) v1(117.25,13.75) 106.75,13.75 92.75,27.75 92.75,36.75 95,39 v1(95,41.25)
AD_UP_1: length 32.6
  TOP w0.2: U8.4 76,35.75 76.67,36.42 76.67,39.86 76.53,40 TP10.1 74.15,40 73,41.15 C30.1 R29.1 ; 74.05,35.8 73,35.8 72.7,35.5 72.7,32.9 76.5,29.1 76.5,24.5 77,24 77,22 76.4,21.4 76.4,20 76.1,19.7 U2.32
AD_VDC_1: length 40.9
  TOP w0.2: D1.1 54.6,2.85 57.2,5.45 57.2,6.95 57.7,7.45 57.7,16.6 57.95,16.85 57.95,20.75 59.25,22.05 63.3,22.05 63.95,21.4 72.55,21.4 72.7,21.55 U2.35
  TOP w0.5: R4.2 50.6,1.75 R5.1 C37.1 54.1,1.75 D1.1
AD_VP_1: length 32.4
  TOP w0.2: R39.1 C33.1 TP12.1 71.55,40 72.95,38.6 75.75,38.6 75.95,38.4 75.95,37.85 75.15,37.05 U8.6 72.8,37.05 72,36.25 72,33 76,29 76,24.25 76.5,23.75 76.5,22.25 75.35,21.1 U2.33
AD_WP_1: length 29.8
  TOP w0.2: U2.34 73.6,22.45 73.6,24 75.55,25.95 75.55,28.85 70.1,34.3 70.1,36.7 69.1,37.7 U8.8 67.95,38.3 67.5,38.75 65.25,38.75 65,39 TP13.1 65,41.5 65.5,42 C34.1 R46.1
COMMD: length 68.4
  TOP w0.2: J7.6 87.25,57.48 89.1,55.63 89.1,38.6 88.64,38.13 J6.10 85.14,38.13 85,38 v1(85,37.5) ; U2.40 68.7,23.55 68.25,24 v1(68.25,24.75) ; v1(85,30) 86.65,28.35 R18.6
  BOTTOM w0.2: v1(85,30) 85,30.85 86.8,32.65 86.8,36.45 85.75,37.5 v1(85,37.5) 79.7,37.5 78.8,36.6 78.8,29 74.95,25.15 68.65,25.15 v1(68.25,24.75)
DIAG: length 15.2
  TOP w0.4: U1.18 56.25,22.4
  TOP w0.5: R43.1 59.6,32.27 59.6,27.85 59.25,27.5 57,27.5 56.75,27.25 56.75,22.9 56.25,22.4
GPIO_MAIN: length 59.8
  TOP w0.2: U2.18 70.4,10.55 v1(70.4,9.5)
  BOTTOM w0.2: J7.8 85.77,48.73 88.5,46 88.5,27.75 85.95,25.2 81.85,25.2 76.15,19.5 73.1,19.5 69.95,16.35 69.95,9.95 v1(70.4,9.5)
KEY_1: length 75.3
  TOP w0.2: J7.5 84.5,56.21 87.74,56.21 88.7,55.25 88.7,38.91 88.56,38.77 85.17,38.77 84.53,38.13 J6.9 v1(81,38.13) ; U2.41 67.9,23.35 67.25,24 v1(67.25,24.75) ; R18.5 87.45,29.05 v1(85.75,30.75)
  BOTTOM w0.2: v1(67.25,24.75) 68.05,25.55 74.75,25.55 78.4,29.2 78.4,36.9 79.64,38.13 v1(81,38.13) 85.97,38.13 87.2,36.9 87.2,32.2 v1(85.75,30.75)
KEY_3: length 39.6
  TOP w0.2: v1(84.25,29.25) 85.85,27.65 R18.7 ; v1(71.5,24) 71.1,23.6 U2.37 ; J6.11 v1(81,36.87)
  BOTTOM w0.2: v1(84.25,29.25) 84.25,30.8 86.4,32.95 86.4,36.15 85.69,36.87 v1(81,36.87) 79.86,36.87 79.2,36.2 79.2,28.8 75.15,24.75 72.25,24.75 v1(71.5,24)
KEY_4: length 63.7
  TOP w0.2: R18.8 85.05,26.95 v1(83.5,28.5) ; U2.12 65.5,9.89 65.36,9.75 v1(64.75,9.75) ; J6.12 85.11,36.87 85,36.75 v1(85,36.25)
  BOTTOM w0.2: v1(83.5,28.5) 83.5,30.75 86,33.25 86,35.7 85.45,36.25 v1(85,36.25) 80,36.25 79.6,35.85 79.6,28.6 75.35,24.35 72.6,24.35 72.25,24 72.25,23.75 71.9,23.4 67.7,23.4 66.6,24.5 64.25,24.5 63.75,24 63.75,23.5 66.6,20.65 66.6,11.6 v1(64.75,9.75)
KEY_A: length 35.7
  TOP w0.2: J6.13 v1(81,35.59) ; U2.36 71.9,23.3 72.35,23.75 v1(73,23.75) ; v1(82.75,27.75) 82.97,27.4 R19.1
  BOTTOM w0.2: v1(82.75,27.75) 82.75,30.6 85.6,33.45 85.6,35.3 85.25,35.65 81.42,35.65 v1(81,35.59) 80.44,35.59 80,35.15 80,28.4 75.35,23.75 v1(73,23.75)
KEYX_1: length 32.8
  TOP w0.2: v1(100,45.75) R50.1 99.75,47 99.75,50.1 S_SW1.2 ; v1(107.5,40) 103.55,40 101.05,37.5 95.25,37.5 94.61,38.13 J9.9
  BOTTOM w0.2: v1(107.5,40) 101.75,45.75 v1(100,45.75)
KEYX_2: length 27.5
  TOP w0.2: v1(109,40) 108.25,40.75 103.5,40.75 100.89,38.13 J9.10 ; v1(106,45.75) R51.1 105.75,47 105.75,50.1 S_SW2.2
  BOTTOM w0.2: v1(106,45.75) 106,44.75 109,41.75 v1(109,40)
KEYX_3: length 33.4
  TOP w0.2: J9.11 94.64,36.87 95.27,36.23 101.48,36.23 104.25,39 110.5,39 v1(112,40.5) ; S_SW3.2 111.75,50.1 111.75,47 R52.1 v1(112,45.75)
  BOTTOM w0.2: v1(112,40.5) v1(112,45.75)
KEYX_4: length 33.5
  TOP w0.2: S_SW4.2 117.75,50.1 117.75,47 R53.1 v1(118,45.75) ; J9.12 101.22,36.87 103.75,39.4 109.9,39.4 v1(110.25,39.75)
  BOTTOM w0.2: v1(110.25,39.75) 111,39.75 111.75,39 113,39 118,44 v1(118,45.75)
KEYX_A: length 50.5
  TOP w0.2: VR1.2 110.12,4.62 C38.1 107.5,2 104.75,2 101.75,5 101.75,34 100.79,34.96 94.79,34.96 94.16,35.59 J9.13
LED1: length 41.1
  TOP w0.2: U2.20 71.9,9.1 73,8 v1(74.75,8) ; J6.17 81.4,33.05 80.8,32.45 80.8,24.85 85.5,20.15 85.5,13.75 v1(84.75,13)
  BOTTOM w0.2: v1(84.75,13) 81.75,13 79.1,10.35 77.1,10.35 v1(74.75,8)
LED1X: length 44.4
  TOP w0.2: v1(100.5,31) 99.08,32.42 95.33,32.42 94.69,33.05 J9.17 ; U7.1 v1(93.25,61)
  BOTTOM w0.2: v1(100.5,31) 99.75,31 97,33.75 97,41.65 92.5,46.15 92.5,59 93.25,59.75 v1(93.25,61)
LED2: length 44.5
  TOP w0.2: v1(84.75,12) 86,13.25 86,20.25 81.2,25.05 81.2,32.2 81.42,32.42 84.77,32.42 85.41,33.05 J6.18 ; U2.21 72.7,9.3 73.25,8.75 75,8.75 v1(75.75,8)
  BOTTOM w0.2: v1(84.75,12) 81.5,12 79.45,9.95 77.7,9.95 v1(75.75,8)
LED2X: length 39
  TOP w0.2: J9.18 99.44,33.05 v1(100.5,32) ; U7.3 v1(94.25,61)
  BOTTOM w0.2: v1(94.25,61) 94.25,59.8 93,58.55 93,46.25 97.5,41.75 97.5,34.25 99.75,32 v1(100.5,32)
LED3: length 38.9
  TOP w0.2: v1(76.75,8) 75.5,9.25 73.75,9.25 73.5,9.5 U2.22 ; v1(84.75,11) 86.5,12.75 86.5,20.35 81.7,25.15 81.7,31.5 81.98,31.79 J6.19
  BOTTOM w0.2: v1(76.75,8) 78.3,9.55 79.8,9.55 81.25,11 v1(84.75,11)
LED3X: length 39.7
  TOP w0.2: v1(95,31.75) 94.58,31.79 J9.19 ; v1(92.5,60.25) 92.5,63.5 94.25,65.25 U7.6
  BOTTOM w0.2: v1(92.5,60.25) 92,59.75 92,46.05 96.5,41.55 96.5,34.5 95,33 v1(95,31.75)
NBOOT: length 63.3
  TOP w0.2: J6.7 80.81,39.41 80,38.6 80,24.45 84,20.45 v1(84,17) ; U2.11 63.65,11.9 63.15,11.4 62.4,11.4 R17.2 v1(61.5,10.5)
  BOTTOM w0.2: v1(84,17) 82,17 81.8,17.2 74.55,17.2 73.2,15.85 73.2,8.55 71.4,6.75 64.15,6.75 61.5,9.4 v1(61.5,10.5)
NBOOTX: length 35
  TOP w0.2: J9.7 94.84,39.41 95.48,38.77 100.77,38.77 103.25,41.25 114.25,41.25 118.75,36.75 118.75,33.75 119,33.5 R22.2 120.57,33.5 JP1.1
NEMG: length 49.2
  TOP w0.2: U2.7 62.8,15.7 v1(62.5,15.4)
  TOP w0.3: U8.14 66.55,33.8 R35.2 v1(66.5,34.75) ; v1(73.5,33) 73.75,33 74.05,33.3 U8.1 74.95,33.8 75.1,33.95 75.1,34.25 74.9,34.45 U8.2
  TOP w0.5: R35.2 65.75,33.75 65,33 TP11.1 R43.2
  BOTTOM w0.2: v1(66.5,34.75) 65.25,33.5 61.75,33.5 59.4,31.15 59.4,23.35 60.4,22.35 61.85,22.35 64.15,20.05 64.15,17.05 v1(62.5,15.4)
  BOTTOM w0.3: v1(66.5,34.75) 68.25,33 v1(73.5,33)
NRESET: length 67
  TOP w0.2: U5.4 75.12,60.75 C27.1 R14.1 73.17,61.27 D2.1 72.15,60.25 R16.1 70.75,58.9 73.15,56.5 78.11,56.5 87,47.61 J6.2 85.22,43.22 84.58,42.58 80.78,42.58 80.25,42.05 80.25,41.25 78.4,39.4 78.4,22.45 76.8,20.85 76.8,19.55 76.15,18.9 U2.31
NRESETX: length 41.9
  TOP w0.2: J9.2 99.97,43.22 100.5,43.75 124,43.75 v1(124.25,43.5) ; v1(125,55.5) 125.4,55.38 J5.10
  BOTTOM w0.2: v1(124.25,43.5) 125,44.25 v1(125,55.5)
NRESIN: length 14.5
  TOP w0.2: U5.2 78.2,60.25 78.4,60.45 78.4,61.23 R54.2 78.5,62.25 79.75,61 79.75,57.1 81.91,54.94 J7.7
NSD: length 40.8
  TOP w0.2: U1.22 55.8,19.2 56,19 v1(56.5,19) 57.3,19.8 57.3,20.7 57.75,21.15 R13.1 ; U2.19 71.1,8 70.8,7.7 64.2,7.7 63.8,8.1 62,8.1 60.9,9.2 60.9,14.75 v1(61.3,15.15)
  BOTTOM w0.2: v1(56.5,19) 58,19 60.95,21.95 61.55,21.95 63.75,19.75 63.75,17.5 61.4,15.15 v1(61.3,15.15)
NSYNC_SPI: length 31.7
  TOP w0.2: U2.42 67.1,23.15 v1(66.5,23.75) ; v1(85,35) 85,35.5 85.09,35.59 J6.14
  BOTTOM w0.2: v1(66.5,23.75) 67.25,23 75.2,23 80.4,28.2 80.4,34.65 80.65,34.9 83.2,34.9 83.3,35 v1(85,35)
NSYNC_SPIX: length 61.4
  TOP w0.2: v1(102,35.25) 101.59,35.25 101.25,35.59 J9.14
  BOTTOM w0.2: J4.3 J4.3-2 110.32,72.07 95,56.75 95,46.55 102,39.55 v1(102,35.25)
RELAY: length 99.1
  TOP w0.2: U2.8 63.55,14.8 62.04,14.8 61.9,14.94 61.9,15.6 61.65,15.85 61.15,15.85 60.5,15.2 60.5,8.75 v1(61.25,8) 61.55,7.7 63.6,7.7 64,7.3 77,7.3 78.25,6.05 80.9,6.05 81.25,5.7 TP1.1 ; J6.8 85.16,39.41 84.52,38.77 80.77,38.77 80.4,38.4 80.4,24.65 84.75,20.3 v1(84.75,16.25)
  BOTTOM w0.2: v1(84.75,16.25) 82,16.25 81.45,16.8 74.75,16.8 73.6,15.65 73.6,8.35 71.45,6.2 63.05,6.2 v1(61.25,8)
RELAYX: length 49.4
  TOP w0.2: J9.8 100.66,39.41 103,41.75 114.5,41.75 119,37.25 125,37.25 126.5,35.75 126.5,23.5 J8.4
RXD_UA_MCU: length 66.9
  TOP w0.2: U2.17 v1(69.5,9.5)
  BOTTOM w0.2: v1(69.5,9.5) 69.5,16.9 72.55,19.95 75.95,19.95 81.7,25.7 85.7,25.7 88.1,28.1 88.1,45.4 81.75,51.75 81.75,58.5 82.41,59.16 J7.3
SCLK_SPI: length 33.3
  TOP w0.2: v1(85,33.75) 85,34.18 85.14,34.33 J6.16 ; U2.44 65.5,22.75 v1(64.5,23.75)
  BOTTOM w0.2: v1(85,33.75) 81.94,33.75 81.3,33.11 81.3,27.9 75.6,22.2 66.05,22.2 v1(64.5,23.75)
SCLK_SPIX: length 58.9
  TOP w0.2: J9.16 100.09,34.33 v1(100.5,34.25)
  BOTTOM w0.2: v1(100.5,34.25) 100.5,39.85 94,46.35 94,57.5 105.24,68.74 J4.5-2 J4.5
SDO_SPI: length 28.1
  TOP w0.2: v1(81,34.25) 81.41,34.33 J6.15 ; v1(65.5,23.75) 66.3,22.95 U2.43
  BOTTOM w0.2: v1(65.5,23.75) 66.65,22.6 75.4,22.6 80.8,28 80.8,33.9 v1(81,34.25)
SDO_SPIX: length 65.6
  TOP w0.2: J9.15 94.67,34.33 95.31,33.69 100.06,33.69 v1(100.5,33.25)
  BOTTOM w0.2: v1(100.5,33.25) 101.25,34 101.25,39.7 94.5,46.45 94.5,57.1 107.78,70.38 J4.4-2 J4.4
SWCLK: length 54.7
  TOP w0.2: U2.14 67.1,9.85 v1(65.75,8.5) ; J6.5 80.88,40.67 79.2,39 79.2,24.05 82,21.25 v1(82,18.5)
  BOTTOM w0.2: v1(65.75,8.5) 66.35,9.1 67.03,9.1 68.38,7.75 71.27,7.75 72.4,8.88 72.4,16.25 74.15,18 81.5,18 v1(82,18.5)
SWCLKX: length 53.2
  TOP w0.2: J5.4 125.42,59.2 v1(125,59.25) ; J9.5 94.58,40.67 95.21,40.04 100.29,40.04 102.5,42.25 120.75,42.25 v1(122.5,40.5)
  BOTTOM w0.2: v1(125,59.25) 122.5,56.75 v1(122.5,40.5)
SWDIO: length 58.7
  TOP w0.2: v1(83,17.75) 83,20.85 79.6,24.25 79.6,38.8 80.84,40.04 84.54,40.04 85.17,40.67 J6.6 ; v1(66.75,8.5) 67.9,9.65 U2.15
  BOTTOM w0.2: v1(66.75,8.5) 68,7.25 71.33,7.25 72.8,8.72 72.8,16.05 74.35,17.6 82,17.6 82.15,17.75 v1(83,17.75)
SWDIOX: length 51.3
  TOP w0.2: J5.2 125.28,60.47 v1(125,60.75) ; v1(124.25,41.5) 123,42.75 102,42.75 99.92,40.67 J9.6
  BOTTOM w0.2: v1(124.25,41.5) 126.25,43.5 126.25,59.5 v1(125,60.75)
SWV: length 59.1
  TOP w0.2: v1(64.75,8.5) 66.3,10.05 U2.13 ; J6.4 85.19,41.95 84.56,41.31 80.91,41.31 78.8,39.2 78.8,23.85 81,21.65 v1(81,19.25)
  BOTTOM w0.2: v1(64.75,8.5) 65.2,8.8 65.9,9.5 67.2,9.5 68.5,8.2 71.15,8.2 71.8,8.85 71.8,16.25 73.95,18.4 80.15,18.4 v1(81,19.25)
SWVX: length 46.4
  TOP w0.2: J9.4 99.75,41.95 101.06,43.25 123.5,43.25 v1(124.25,42.5) ; v1(125,57.75) 125.33,57.75 125.5,57.92 J5.6
  BOTTOM w0.2: v1(124.25,42.5) 125.75,44 125.75,57 v1(125,57.75)
TXD_UA_MCU: length 72.2
  TOP w0.2: v1(68.6,9.5) 68.7,9.9 U2.16
  BOTTOM w0.2: J7.4 84.54,61.25 82.5,61.25 81.25,60 81.25,51.5 87.7,45.05 87.7,28.5 85.35,26.15 81.4,26.15 75.8,20.55 72.2,20.55 68.6,16.95 v1(68.6,9.5)
UH_1: length 39.4
  TOP w0.2: v1(56.5,13) 55.9,13.6 U1.29 ; U2.1 62.8,20.5 61.95,21.35 v1(61.25,21.35) 59.5,21.35 58.35,20.2 58.35,16.65 58.1,16.4 58.1,6.8 60.25,4.65 TP5.1
  BOTTOM w0.2: v1(56.5,13) 59.45,15.95 61.6,15.95 63.35,17.7 63.35,19.55 62.1,20.8 61.8,20.8 v1(61.25,21.35)
UL_1: length 36
  TOP w0.2: U1.26 v1(56.5,16) ; U2.2 62.9,19.7 62.55,20.05 v1(62,20.05) 61.3,20.75 59.95,20.75 58.75,19.55 58.75,16.45 58.5,16.2 58.5,6.98 59.78,5.7 62.6,5.7 63.75,4.55 TP14.1
  BOTTOM w0.2: v1(56.5,16) 57.65,17.15 61,17.15 61.55,17.7 61.55,19.6 v1(62,20.05)
VH_1: length 39.8
  TOP w0.2: U2.3 63.17,18.9 62.92,19.15 v1(62.5,19.15) 62.05,19.15 60.85,20.35 60.15,20.35 59.15,19.35 59.15,16.25 58.9,16 58.9,7.15 59.95,6.1 62.8,6.1 63.2,5.7 66.1,5.7 67.25,4.55 TP4.1 ; U1.28 56.1,14.4 v1(56.5,14)
  BOTTOM w0.2: v1(56.5,14) 58.85,16.35 61.4,16.35 62.95,17.9 62.95,18.7 v1(62.5,19.15)
VL_1: length 39.7
  TOP w0.2: TP15.1 70.75,4.6 69.25,6.1 63.4,6.1 63,6.5 60.15,6.5 59.3,7.35 59.3,15.8 59.55,16.05 59.55,19.15 60.15,19.75 v1(60.6,19.75) 61.8,18.55 62.7,18.55 63.15,18.1 U2.4 ; U1.25 55.75,16.8 55.95,17 v1(56.5,17)
  BOTTOM w0.2: v1(60.6,19.75) 61.15,19.2 61.15,17.9 60.8,17.55 57.05,17.55 v1(56.5,17)
VP+: length 101.8
  TOP w0.4: U1.4 45.75,17.6
  TOP w0.5: R1.1 v1(39.25,75)
  TOP w1: R2.1 45.9,5.25 45.9,6.25
  TOP w3: F1.2 24.5,46.45 33.55,55.5 C36.1 41.25,50.2 46.25,45.2 46.25,6.25
  BOTTOM w0.5: C36.1 41.25,73 v1(39.25,75)
WH_1: length 41.4
  TOP w0.2: TP3.1 74.25,4.6 72.35,6.5 63.6,6.5 63.2,6.9 60.45,6.9 59.7,7.65 59.7,15.6 59.95,15.85 59.95,18.6 60.15,18.8 60.75,18.8 61.6,17.95 v1(62.15,17.95) 62.8,17.3 U2.5 ; U1.27 55.75,15.2 55.95,15 v1(56.5,15)
  BOTTOM w0.2: v1(62.15,17.95) 62.15,17.7 61.2,16.75 58.25,16.75 v1(56.5,15)
WL_1: length 40.7
  TOP w0.2: v1(56.5,17.95) 56.1,17.95 55.75,17.6 U1.24 ; TP16.1 77.75,4.6 75.45,6.9 63.8,6.9 63.4,7.3 60.65,7.3 60.1,7.85 60.1,15.4 60.55,15.85 v1(60.55,18.15) 61.25,17.45 61.25,17.2 61.95,16.5 U2.6
  BOTTOM w0.2: v1(56.5,17.95) 59.05,17.95 59.25,18.15 v1(60.55,18.15)
N524300: length 4.3
  TOP w0.2: U2.26 75.4,14.85 77.8,14.85 Y1.3 78.25,15.3 C24.1 78.25,16.5
N524312: length 8.4
  TOP w0.2: Y1.1 79.6,12.6 79.25,12.25 C16.1 78.65,10.4 77.25,10.4 76.75,10.9 76.75,13 76.45,13.3 U2.24
N530340: length 4
  TOP w0.2: C20.1 77.75,17.75 77.1,17.1 77.1,16.9 75.9,15.7 U2.27
N530678: length 4.8
  TOP w0.2: U2.30 75.95,18.1 77.2,19.35 77.2,20.07 C21.1
N538715: length 5.1
  TOP w0.4: C9.1 40.88,16.38 42.05,15.2 U1.3
N539007: length 5.1
  TOP w0.4: U1.6 40.9,20.8 39.83,21.88 C10.1
N539151: length 4.7
  TOP w0.4: U1.7 38.33,23.2 C12.1
N541275: length 13.4
  TOP w3: J2.2 10,32 18.23,23.77 L3.1
N541304: length 11.9
  TOP w3: J2.3 11.75,21 16.23,16.52 L2.1
N541340: length 18.9
  TOP w3: J2.1 13.25,43 15.42,40.83 15.42,34.1 L4.1
N542318: length 19.9
  TOP w3: F1.1 22.75,82.05 13.2,72.5 J1.1
N545527: length 62.6
  TOP w0.2: R11.2 26.25,35.75 25.95,36.05 25.95,37.45 v1(26.25,37.75)
  TOP w0.4: U1.9 40.25,26.4
  TOP w0.5: v1(70,54.75) R41.2
  BOTTOM w0.2: v1(70,54.75) 70.3,55.05 70.3,55.6 68.65,57.25 61.6,57.25 45.85,41.5 35.15,41.5 31.95,38.3 26.1,38.3 26,38.2 26,38 v1(26.25,37.75)
  vias: v1(33.5,10.25) v1(33.5,9.25) v1(34.5,10.25) v1(34.5,9.25) v1(34.75,33.5) v1(34.75,32.5) v1(35.5,10.25) v1(35.5,9.25) v1(35.75,33.5) v1(35.75,32.5) v1(36.75,33.5) v1(36.75,32.5)
N16763341: length 7.5
  TOP w0.4: U1.14 55.6,25.6
  TOP w0.5: 55.6,25.6 56,26 56,28.75 56.5,29.25 C15.1 57.62,29.25 58.25,28.62 C14.1
N16816065: length 18.1
  TOP w0.3: C35.1 66.55,37.05 U8.9 ; U8.7 74.95,37.7 v1(75.25,38) ; U8.5 75.4,36.4 v1(75.5,36.5)
  TOP w0.5: v1(66.5,38) C35.1 R48.1 R33.2
  BOTTOM w0.5: v1(66.5,38) v1(75.25,38) 75.5,37.75 v1(75.5,36.5)
N16817615: length 14.5
  TOP w0.2: R42.1 R41.1 70,52.9 D5.3 71.15,51.1 70.55,50.5 65.45,50.5 64.75,49.8 64.75,48.55 65.4,47.9 U6.10
N16817617: length 8.9
  TOP w0.2: R39.2 70.5,47.7 69,49.2 U6.8 66.3,49.2 R37.1
N16817619: length 13.7
  TOP w0.2: U6.9 66.05,48.55 R37.2 65.5,48.5 65.15,48.85 65.15,49.55 65.65,50.05 71.4,50.05 72.2,50.85 72.2,52.3 71.5,53 R38.1
N16818945: length 8.9
  TOP w0.2: U6.5 75.7,47.9 76.35,48.55 76.35,51.05 D4.3 75.5,51.9 R34.1 R32.1
N16818947: length 8
  TOP w0.2: R27.1 74.7,49.2 U6.7 72.65,49.2 72.4,48.95 72.4,44.6 R29.2
N16818953: length 7.5
  TOP w0.2: U6.6 74.85,48.55 74.9,48.5 R27.2 75.45,48.5 75.75,48.8 75.75,50.05 74.45,51.35 74.45,52.05 R28.1
N16823954: length 27.5
  TOP w0.3: v1(74,44.5) 73.55,44.95 U6.1 74.5,45.3 74.65,45.45 74.65,45.8 74.5,45.95 U6.2
  TOP w0.5: R49.2 R42.2 v1(69,54.75) ; v1(75.5,54.75) R34.2
  BOTTOM w0.5: v1(74,44.5) 74,48.25 76.25,50.5 76.25,54 v1(75.5,54.75) 75.5,54.65 74.15,53.3 69.45,53.3 69,53.75 v1(69,54.75)
N16824265: length 11.4
  TOP w0.2: R47.1 R49.1 66.65,52.85 D6.3 66.1,51.2 65.55,51.2 64.25,49.9 64.25,47.55 65.2,46.6 U6.12
N16827190: length 65.5
  TOP w0.2: v1(26.25,40) 25.95,40.3 25.95,41.45 26.5,42 R12.2
  TOP w0.5: v1(74.5,54.75) R32.2
  BOTTOM w0.2: v1(74.5,54.75) 74.1,55.15 74.1,57.25 72.4,58.95 59.75,58.95 45.55,44.75 33.43,44.75 28.18,39.5 26.1,39.5 26.02,39.58 26.02,39.77 v1(26.25,40)
N16827301: length 96.9
  TOP w0.2: v1(24.5,3) 24.2,3.3 24.2,5.15 25.05,6 R10.2
  TOP w0.5: v1(65.5,54.75) R47.2
  BOTTOM w0.2: v1(24.5,3) 24.2,2.7 24.2,2.45 24.55,2.1 51.25,2.1 52.85,3.7 52.85,46.25 63,56.4 64.6,56.4 65.15,55.85 65.15,55.1 v1(65.5,54.75)
N16845509: length 13.1
  TOP w0.2: TST1.1 LED1.1 97.65,62.25 97.15,62.75 97.15,65.85 96.1,66.9 93.9,66.9 93.75,66.75 U7.7
N16847149: length 31.8
  TOP w0.2: U7.2 93.75,63.85 94.6,64.7 95.7,64.7 96.15,64.25 96.15,58.05 98.25,55.95 105.95,55.95 107.6,57.6 107.6,61.35 108.5,62.25 LED3.1 TST3.1
N16847386: length 24.7
  TOP w0.2: U7.5 96.05,66 96.75,65.3 96.75,58.6 99,56.35 100.95,56.35 103.1,58.5 103.1,61.7 103.65,62.25 LED2.1 TST2.1
N16936899: length 2.1
  TOP w0.5: R3.2 LEDP1.1
N16997175: length 4.6
  TOP w0.2: R6.2 R7.1 C13.2 75.25,45.85 74.5,46.6 U6.3
N17594442: length 11
  TOP w0.2: R45.1 63.85,53 63.6,52.75 63.6,47 64.6,46 R44.2 66.05,45.95 U6.13
N17594625: length 3
  TOP w0.2: R44.1 66.3,45.3 U6.14 67.45,44.2 R46.2
N89949821: length 1.8
  TOP w0.2: SW1.2 69.42,59.92 R16.2
N168435951: length 1.5
  TOP w0.5: R1.2 R3.1
N168438761: length 1.3
  TOP w0.5: R4.1 R2.2
N168456521: length 1.8
  TOP w0.2: LED1.2 R25.1
N168457540: length 1.8
  TOP w0.2: LED3.2 R36.1
N168470940: length 1.8
  TOP w0.2: R15.1 LEDP2.1
N168482340: length 1.8
  TOP w0.2: LED2.2 R30.1

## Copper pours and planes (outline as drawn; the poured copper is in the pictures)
AGND on TOP: 70.81,34.05 70.78,34.06 70.75,34.07 70.42,34.4 70.41,34.43 70.4,34.46 70.4,36.7 70.4,36.74 70.35,36.87 70.31,36.91 69.02,38.2 68.51,38.2 68.48,38.21 68.45,38.22 67.32,39.35 67.31,39.38 67.3,39.41 67.3,41.48 67.32,41.53 67.38,41.55 67.48,41.55 68.03,41.55 68.05,41.55 68.45,41.55 68.63,41.62 68.7,41.8 68.7,42.2 68.63,42.38 68.45,42.45 67.78,42.45 67.72,42.47 67.7,42.52 67.7,44.01 67.74,44.12 67.75,44.2 67.75,44.85 67.77,44.9 67.83,44.92 68.05,44.92 68.23,45 68.3,45.17 68.3,48.83 68.32,48.88 68.38,48.9 68.84,48.9 68.87,48.89 68.9,48.88 70.18,47.6 70.19,47.57 70.2,47.54 70.2,44.47 70.19,44.44 70.08,44.32 70.05,44.2 70.05,41.08 70.03,41.02 69.97,41 68.65,41 68.47,40.93 68.4,40.75 68.4,39.25 68.47,39.07 68.65,39 71.52,39 71.55,38.99 71.57,38.98 71.68,38.87 71.69,38.85 71.7,38.82 71.7,34.48 71.69,34.45 71.68,34.43 71.32,34.07 71.3,34.06 71.27,34.05
AGND on TOP: 73.83,41 73.77,41.02 73.75,41.08 73.75,41.48 73.77,41.53 73.83,41.55 74.2,41.55 74.38,41.62 74.45,41.8 74.45,42.2 74.38,42.38 74.2,42.45 73.8,42.45 73.75,42.45 73.53,42.45 73.47,42.47 73.45,42.52 73.45,43.92 73.47,43.98 73.53,44 74,44 74.25,44.07 74.43,44.25 74.47,44.34 74.5,44.43 74.52,44.48 74.57,44.5 74.72,44.5 74.78,44.48 74.8,44.42 74.8,44.05 74.87,43.87 75.05,43.8 76.72,43.8 76.78,43.78 76.8,43.73 76.8,43.48 76.79,43.45 76.88,42.92 77.4,42.77 77.4,42.77 77.71,43.05 77.71,43.45 77.7,43.48 77.7,45.45 77.63,45.63 77.45,45.7 76.33,45.7 76.27,45.72 76.25,45.77 76.25,46.73 76.27,46.78 76.33,46.8 76.95,46.8 77.13,46.87 77.2,47.05 77.2,47.42 77.22,47.48 77.28,47.5 77.47,47.5 77.5,47.49 77.52,47.48 78.48,46.52 78.49,46.5 78.5,46.47 78.5,43.28 78.49,43.25 78.48,43.23 76.27,41.02 76.25,41.01 76.22,41
AGND on TOP: 61.02,34 60.97,34.02 60.95,34.08 60.95,42.43 60.96,42.46 60.97,42.48 64.17,45.68 64.19,45.69 64.22,45.7 65.47,45.7 65.53,45.68 65.55,45.62 65.55,44.8 65.62,44.62 65.8,44.55 66.72,44.55 66.78,44.53 66.8,44.48 66.8,42.38 66.78,42.32 66.72,42.3 65.5,42.3 65.39,42.28 65.29,42.21 64.79,41.71 64.72,41.61 64.7,41.5 64.7,41.08 64.68,41.02 64.62,41 63.15,41 62.97,40.93 62.9,40.75 62.9,38.8 62.89,38.75 62.85,38.73 62.77,38.7 62,38.7 61.83,38.67 61.68,38.57 61.43,38.32 61.33,38.17 61.3,38 61.3,37.72 61.29,37.69 61.18,37.57 61.15,37.45 61.15,35.05 61.22,34.87 61.4,34.8 62.1,34.8 62.28,34.87 62.35,35.05 62.35,36.48 62.37,36.53 62.42,36.55 64.67,36.55 64.73,36.53 64.75,36.48 64.75,35.8 64.82,35.62 65,35.55 65.5,35.55 65.68,35.62 65.75,35.8 65.75,36.17 65.77,36.23 65.83,36.25 65.97,36.25 66.03,36.23 66.05,36.17 66.05,34.98 66.01,34.82 66,34.68 66,34.65 65.98,34.62 65.38,34.02 65.36,34.01 65.33,34
AGND on TOP: 72.4,41 72.35,41 71.28,41 71.22,41.02 71.2,41.08 71.2,41.48 71.22,41.53 71.28,41.55 71.3,41.55 71.7,41.55 71.88,41.62 71.95,41.8 71.95,42.2 71.88,42.38 71.7,42.45 71.03,42.45 70.97,42.47 70.95,42.52 70.95,44.2 70.92,44.32 70.81,44.44 70.8,44.47 70.8,48.99 70.81,49.02 70.82,49.05 72.41,50.64 72.45,50.68 72.49,50.75 72.82,51.08 72.84,51.09 72.87,51.1 74.24,51.1 74.27,51.09 74.3,51.08 74.34,51.03 74.36,51.01 74.36,50.98 74.36,49.65 74.34,49.6 74.29,49.58 72.6,49.58 72.19,49.16 72.12,49.06 72.1,48.95 72.1,44.6 72.12,44.49 72.19,44.39 72.53,44.05 72.54,44.02 72.55,43.99 72.55,41.05 72.52,40.99 72.45,40.98
AGND on BOTTOM: outline of 100 points within 60.85,28.7 77.55,52.05
GND on TOP: outline of 298 points within 57.4,1 89,32.25 ; 1 cut-out
GND on TOP: 54.08,27.75 54.02,27.77 54,27.82 54,31.68 54.01,31.71 54.02,31.74 54.51,32.23 54.54,32.24 54.57,32.25 58.96,32.25 58.99,32.24 59.01,32.23 59.13,32.11 59.14,32.09 59.15,32.06 59.15,31.02 59.13,30.97 59.08,30.95 58.4,30.95 58.24,30.9 58.13,30.72 58.08,30.7 57.3,30.7 57.12,30.63 57.05,30.45 57.05,29.77 57.03,29.72 56.98,29.7 56.5,29.7 56.33,29.67 56.18,29.57 55.68,29.07 55.58,28.92 55.55,28.75 55.55,27.82 55.53,27.77 55.48,27.75
GND on TOP: outline of 350 points within 49.75,22.85 89,84 ; 12 cut-outs
GND on TOP: 57.27,24.95 57.22,24.97 57.2,25.02 57.2,26.98 57.22,27.03 57.27,27.05 59.25,27.05 59.42,27.08 59.57,27.18 59.92,27.53 60.02,27.68 60.05,27.85 60.05,31.93 60.07,31.98 60.12,32 65.93,32 65.98,31.98 66,31.93 66.5,31.5 67,31.93 67.02,31.98 67.07,32 67.42,32 67.48,31.98 67.5,31.93 67.5,29.22 67.49,29.19 67.47,29.16 67.38,29.09 67.25,28.7 67.38,28.41 67.39,28.39 67.4,28.36 67.4,28.32 67.38,28.27 67.33,28.25 65.9,28.25 65.77,28.21 65.65,28.09 65.61,28.07 62.05,28.07 61.87,28 61.8,27.82 61.8,27.78 61.77,27.72 61.7,27.71 61,27.25 61.7,26.79 61.77,26.78 61.8,26.72 61.8,26.68 61.87,26.5 62.05,26.43 65.61,26.43 65.65,26.41 65.77,26.29 65.9,26.25 66.42,26.25 66.48,26.23 66.5,26.18 66.5,25.22 66.49,25.19 66.47,25.16 66.38,25.09 66.31,24.99 66.28,24.96 66.25,24.95 60.48,24.95 60.45,24.96 60.25,25 60.05,24.96 60.02,24.95
GND on BOTTOM: outline of 196 points within 54.25,1 89,84 ; 12 cut-outs
GND on BOTTOM: 56.17,20.25 56.14,20.26 56.11,20.27 55.91,20.48 55.89,20.5 55.88,20.53 55.88,40.17 55.91,40.23 55.96,40.25 59.42,40.25 59.48,40.23 59.5,40.17 59.5,31.71 59.49,31.68 59.48,31.65 59.19,31.36 59.12,31.26 59.1,31.15 59.1,21.13 59.09,21.1 59.08,21.08 58.27,20.27 58.25,20.26 58.22,20.25
GNDX on TOP: 91,83.92 91.02,83.98 91.08,84 128.93,84 128.98,83.98 129,83.92 129,1.07 128.98,1.02 128.93,1 91.08,1 91.02,1.02 91,1.07 ; 45 cut-outs
GNDX on BOTTOM: 91,83.92 91.02,83.98 91.08,84 128.93,84 128.98,83.98 129,83.92 129,1.07 128.98,1.02 128.93,1 91.08,1 91.02,1.02 91,1.07 ; 42 cut-outs
PGND on TOP: 51.33,2.5 51.3,2.51 51.28,2.52 50.9,2.9 50.88,2.93 50.85,2.95 49.62,4.18 49.61,4.2 49.6,4.23 49.6,5.42 49.62,5.48 49.67,5.5 52.52,5.5 52.58,5.48 52.6,5.42 52.6,4.15 52.98,3.77 52.99,3.75 53,3.72 53,2.58 52.98,2.52 52.92,2.5
PGND on TOP: 17.57,4 17.52,4.02 17.5,4.08 17.5,7.92 17.52,7.98 17.57,8 21.93,8 21.98,7.98 22,7.92 22,4.08 21.98,4.02 21.93,4
PGND on TOP: 19.32,40 19.27,40.02 19.25,40.08 19.25,43.92 19.27,43.98 19.32,44 23.68,44 23.73,43.98 23.75,43.92 23.75,40.08 23.73,40.02 23.68,40
PGND on TOP: 19.78,34.25 19.75,34.26 19.73,34.27 19.27,34.73 19.26,34.75 19.25,34.78 19.25,38.17 19.27,38.23 19.32,38.25 23.68,38.25 23.73,38.23 23.75,38.17 23.75,34.33 23.73,34.27 23.68,34.25
PGND on TOP: 4.58,60 4.52,60.02 4.5,60.08 4.5,62.92 4.52,62.98 4.58,63 11.68,63 11.73,62.98 11.75,62.92 11.75,60.08 11.73,60.02 11.68,60
PGND on BOTTOM: 17.78,4 17.75,4.01 17.73,4.02 13.27,8.48 13.26,8.5 13.25,8.53 13.25,49.5 7.02,55.73 7.01,55.75 7,55.78 7,61.67 7.02,61.73 7.08,61.75 9.93,61.75 9.98,61.73 10,61.67 10,57 16.23,50.77 16.24,50.75 16.25,50.72 16.25,44.75 16.75,44.25 20.72,44.25 20.75,44.24 20.77,44.23 21.23,43.77 21.24,43.75 21.25,43.72 21.25,34.53 21.24,34.5 21.23,34.48 21.02,34.27 21,34.26 20.97,34.25 17,34.25 16.25,33.5 16.25,10.75 18.75,8.25 19.68,8.25 19.73,8.23 19.75,8.18 19.75,4.08 19.73,4.02 19.68,4
VP+ on TOP: 45.08,37 45.02,37.02 45,37.08 45,39.67 45.02,39.73 45.08,39.75 47.67,39.75 47.73,39.73 47.75,39.67 47.75,37.08 47.73,37.02 47.67,37
